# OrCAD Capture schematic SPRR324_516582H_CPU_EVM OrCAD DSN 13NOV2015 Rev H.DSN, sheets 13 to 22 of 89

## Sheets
13 SH19 - VAYU USB: size B; rev: A
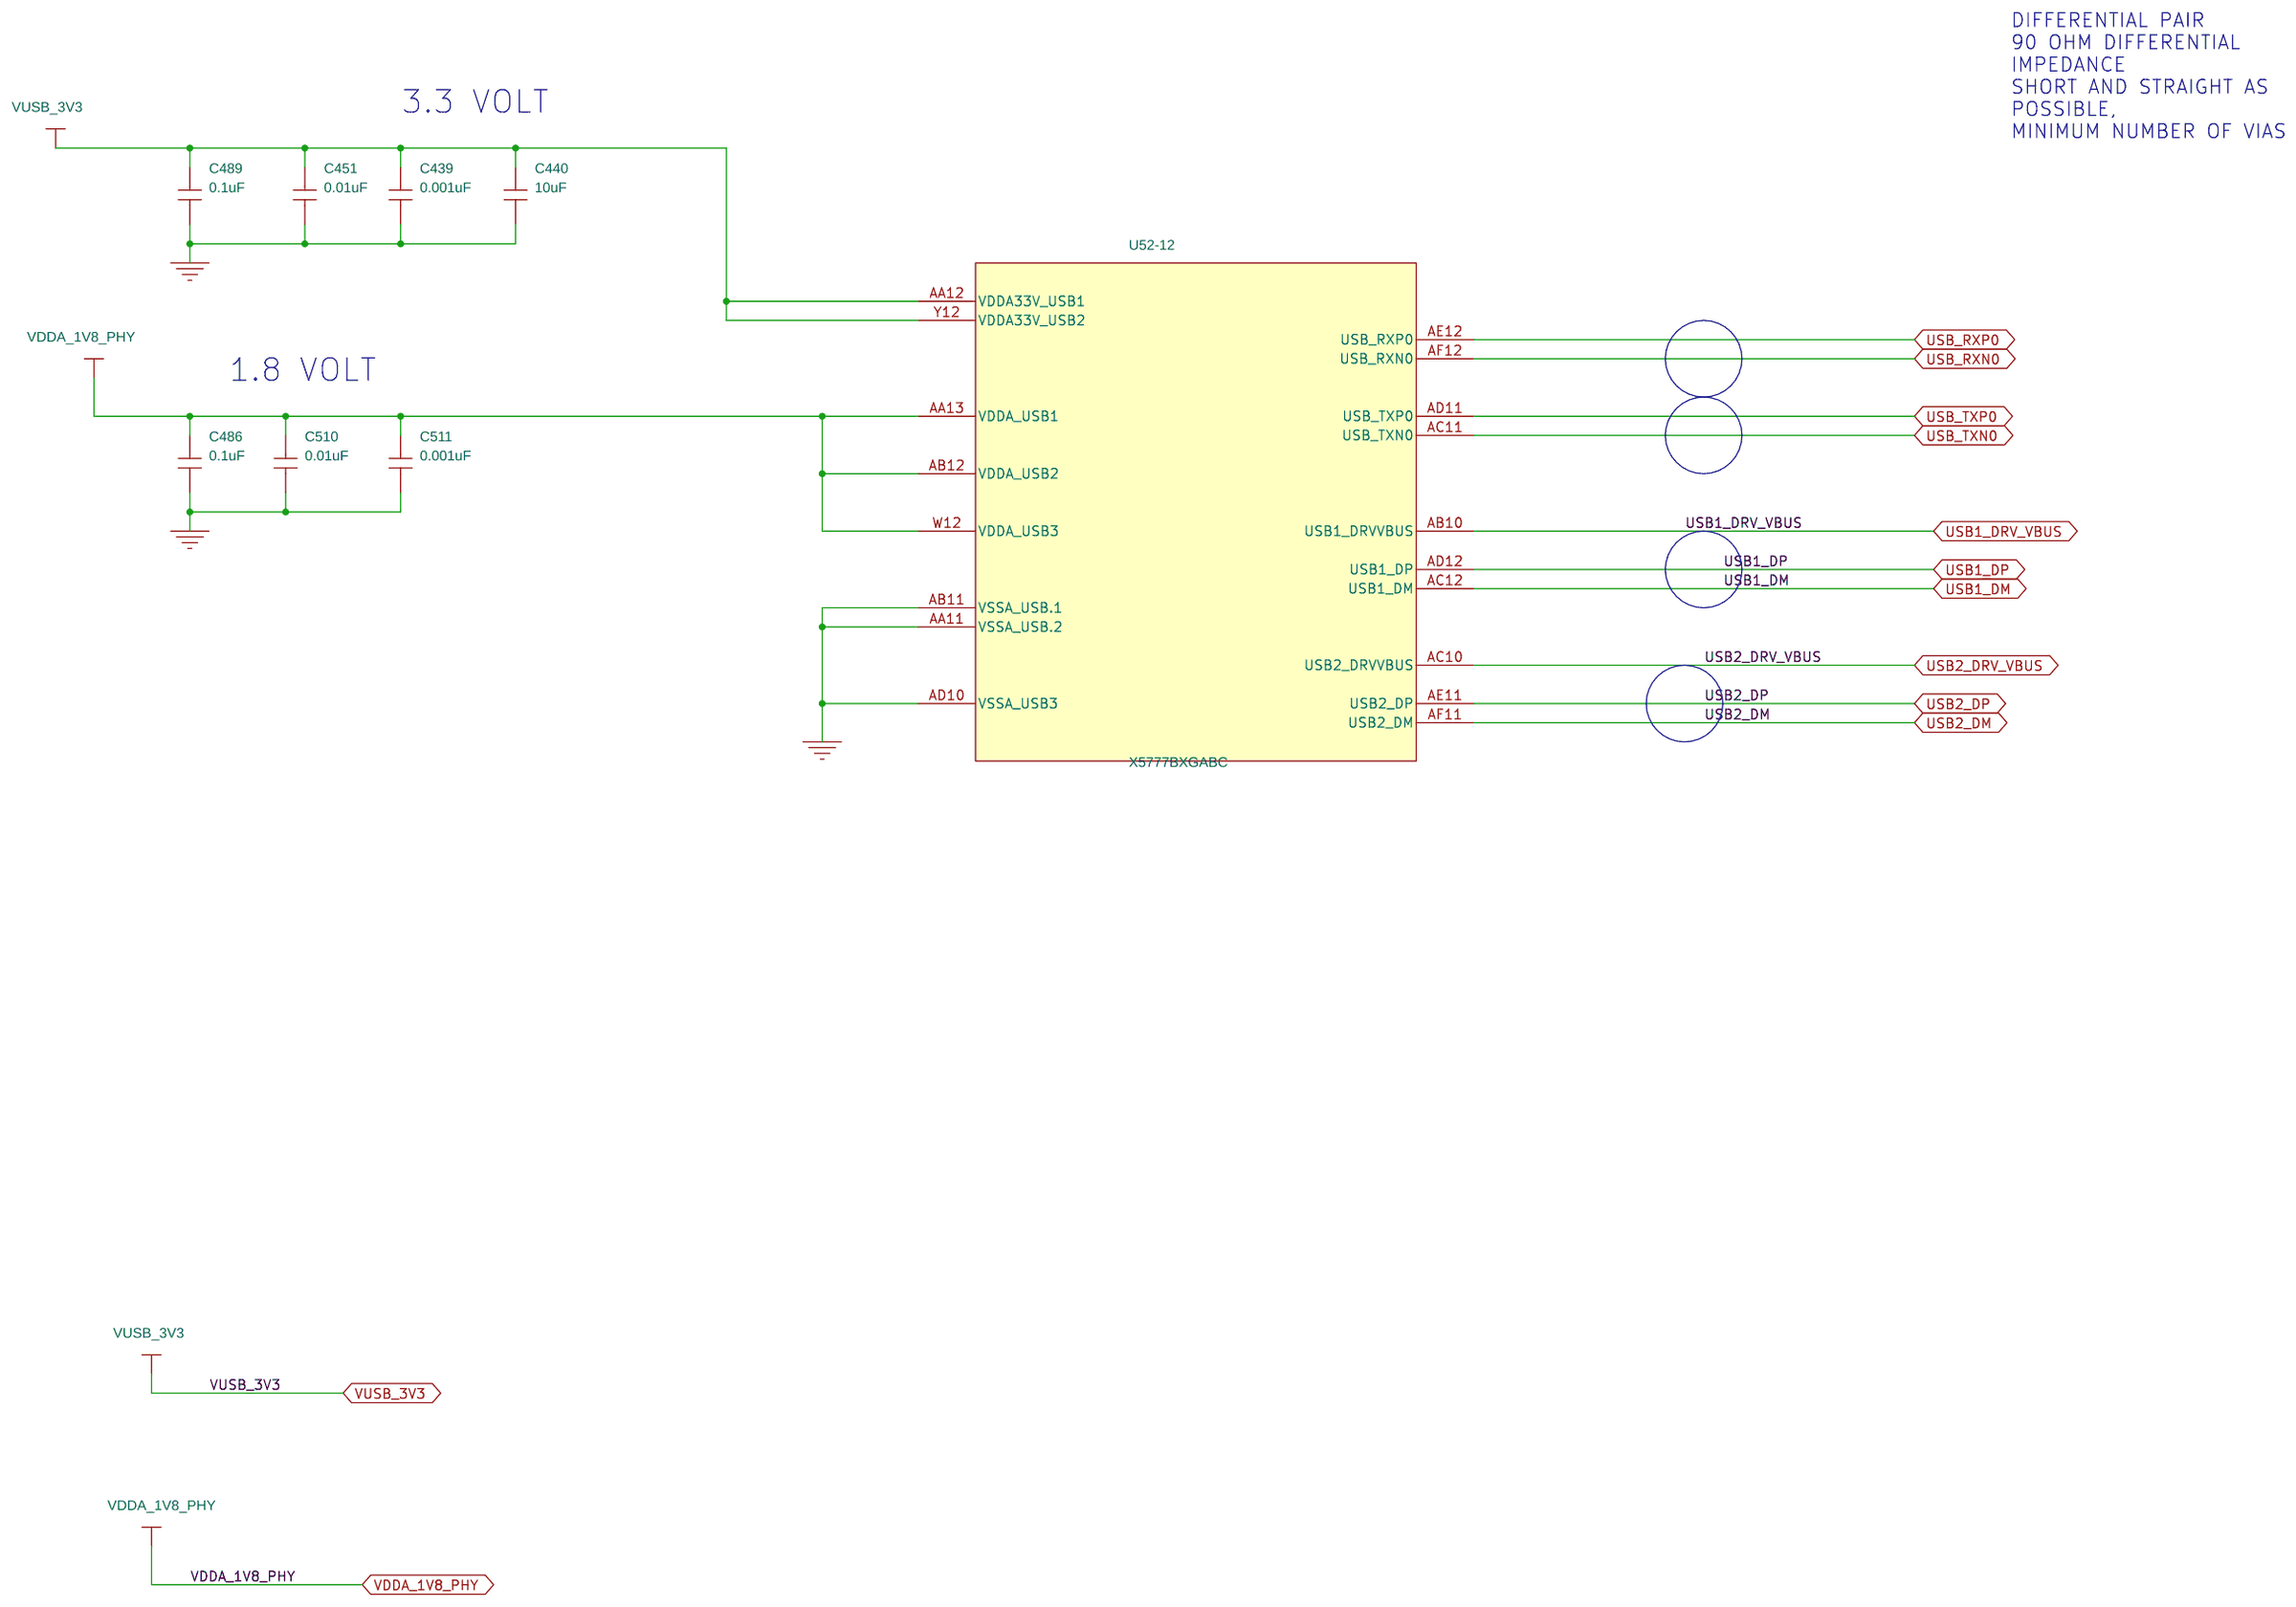
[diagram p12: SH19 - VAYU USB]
14 SH20 - VAYU GPMC: size B; rev: D2
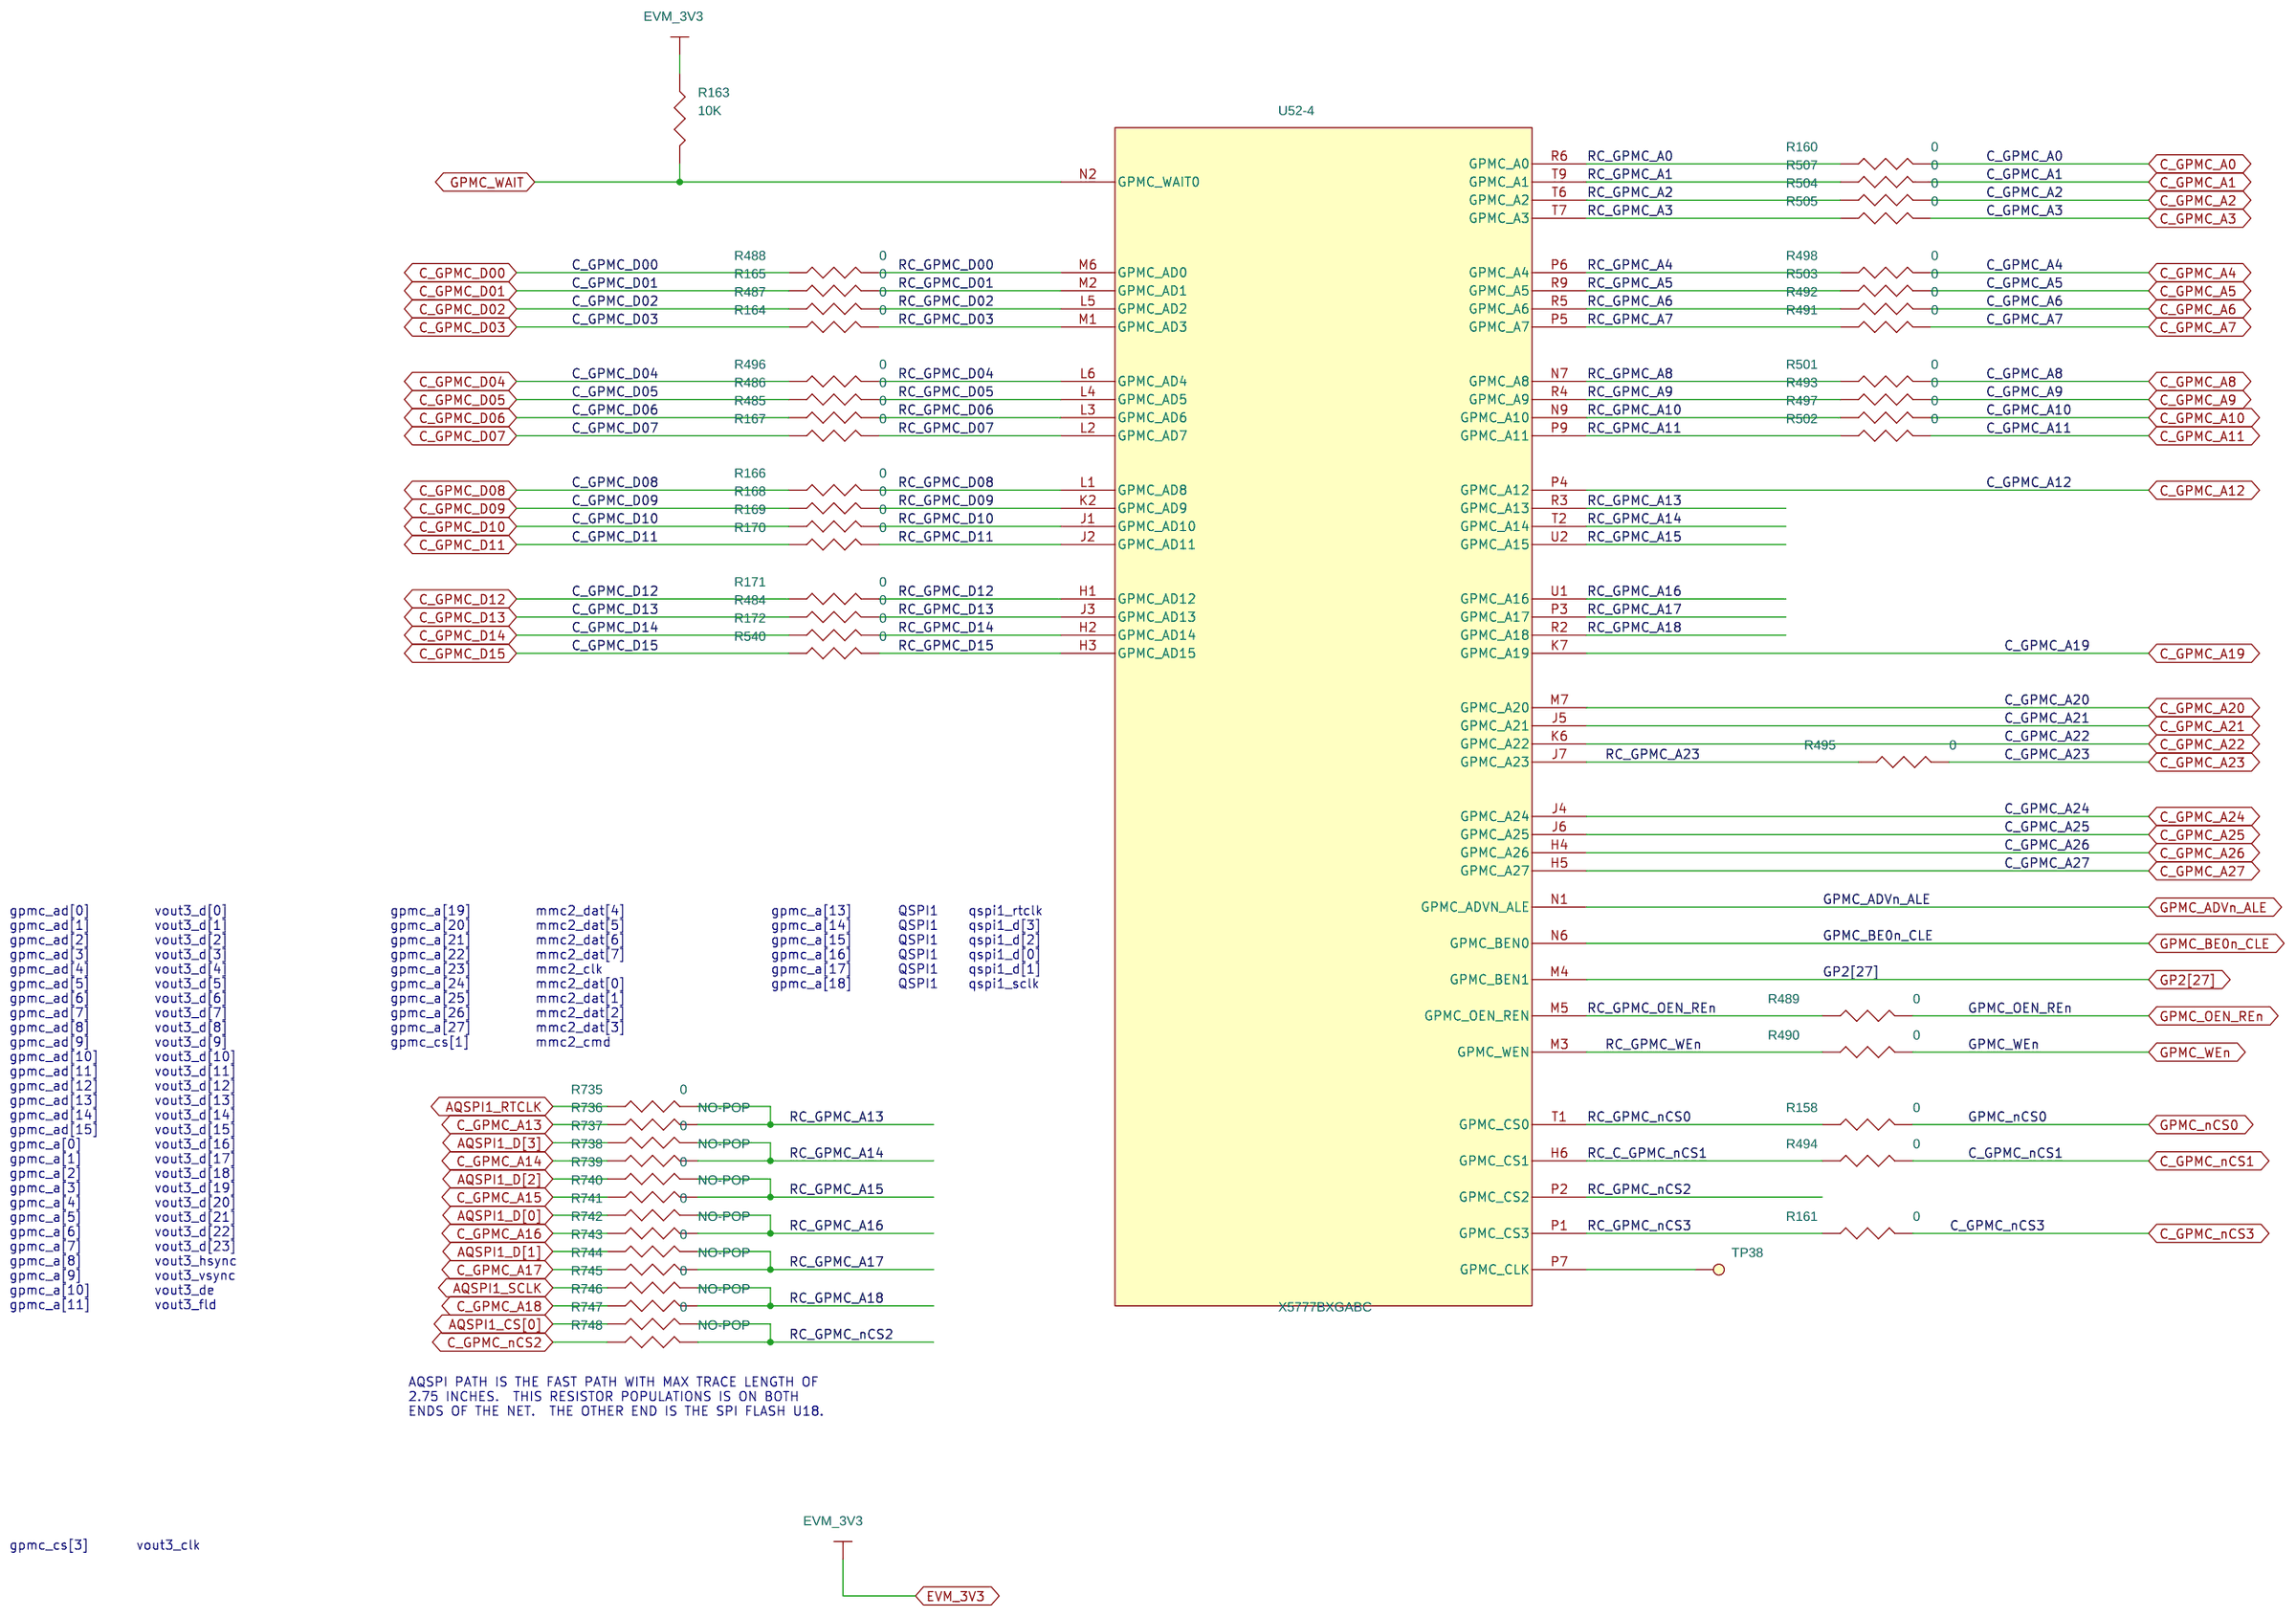
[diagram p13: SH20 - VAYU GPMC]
15 SH21 - GPMC DATA MUX VIDEO: size B; rev: A
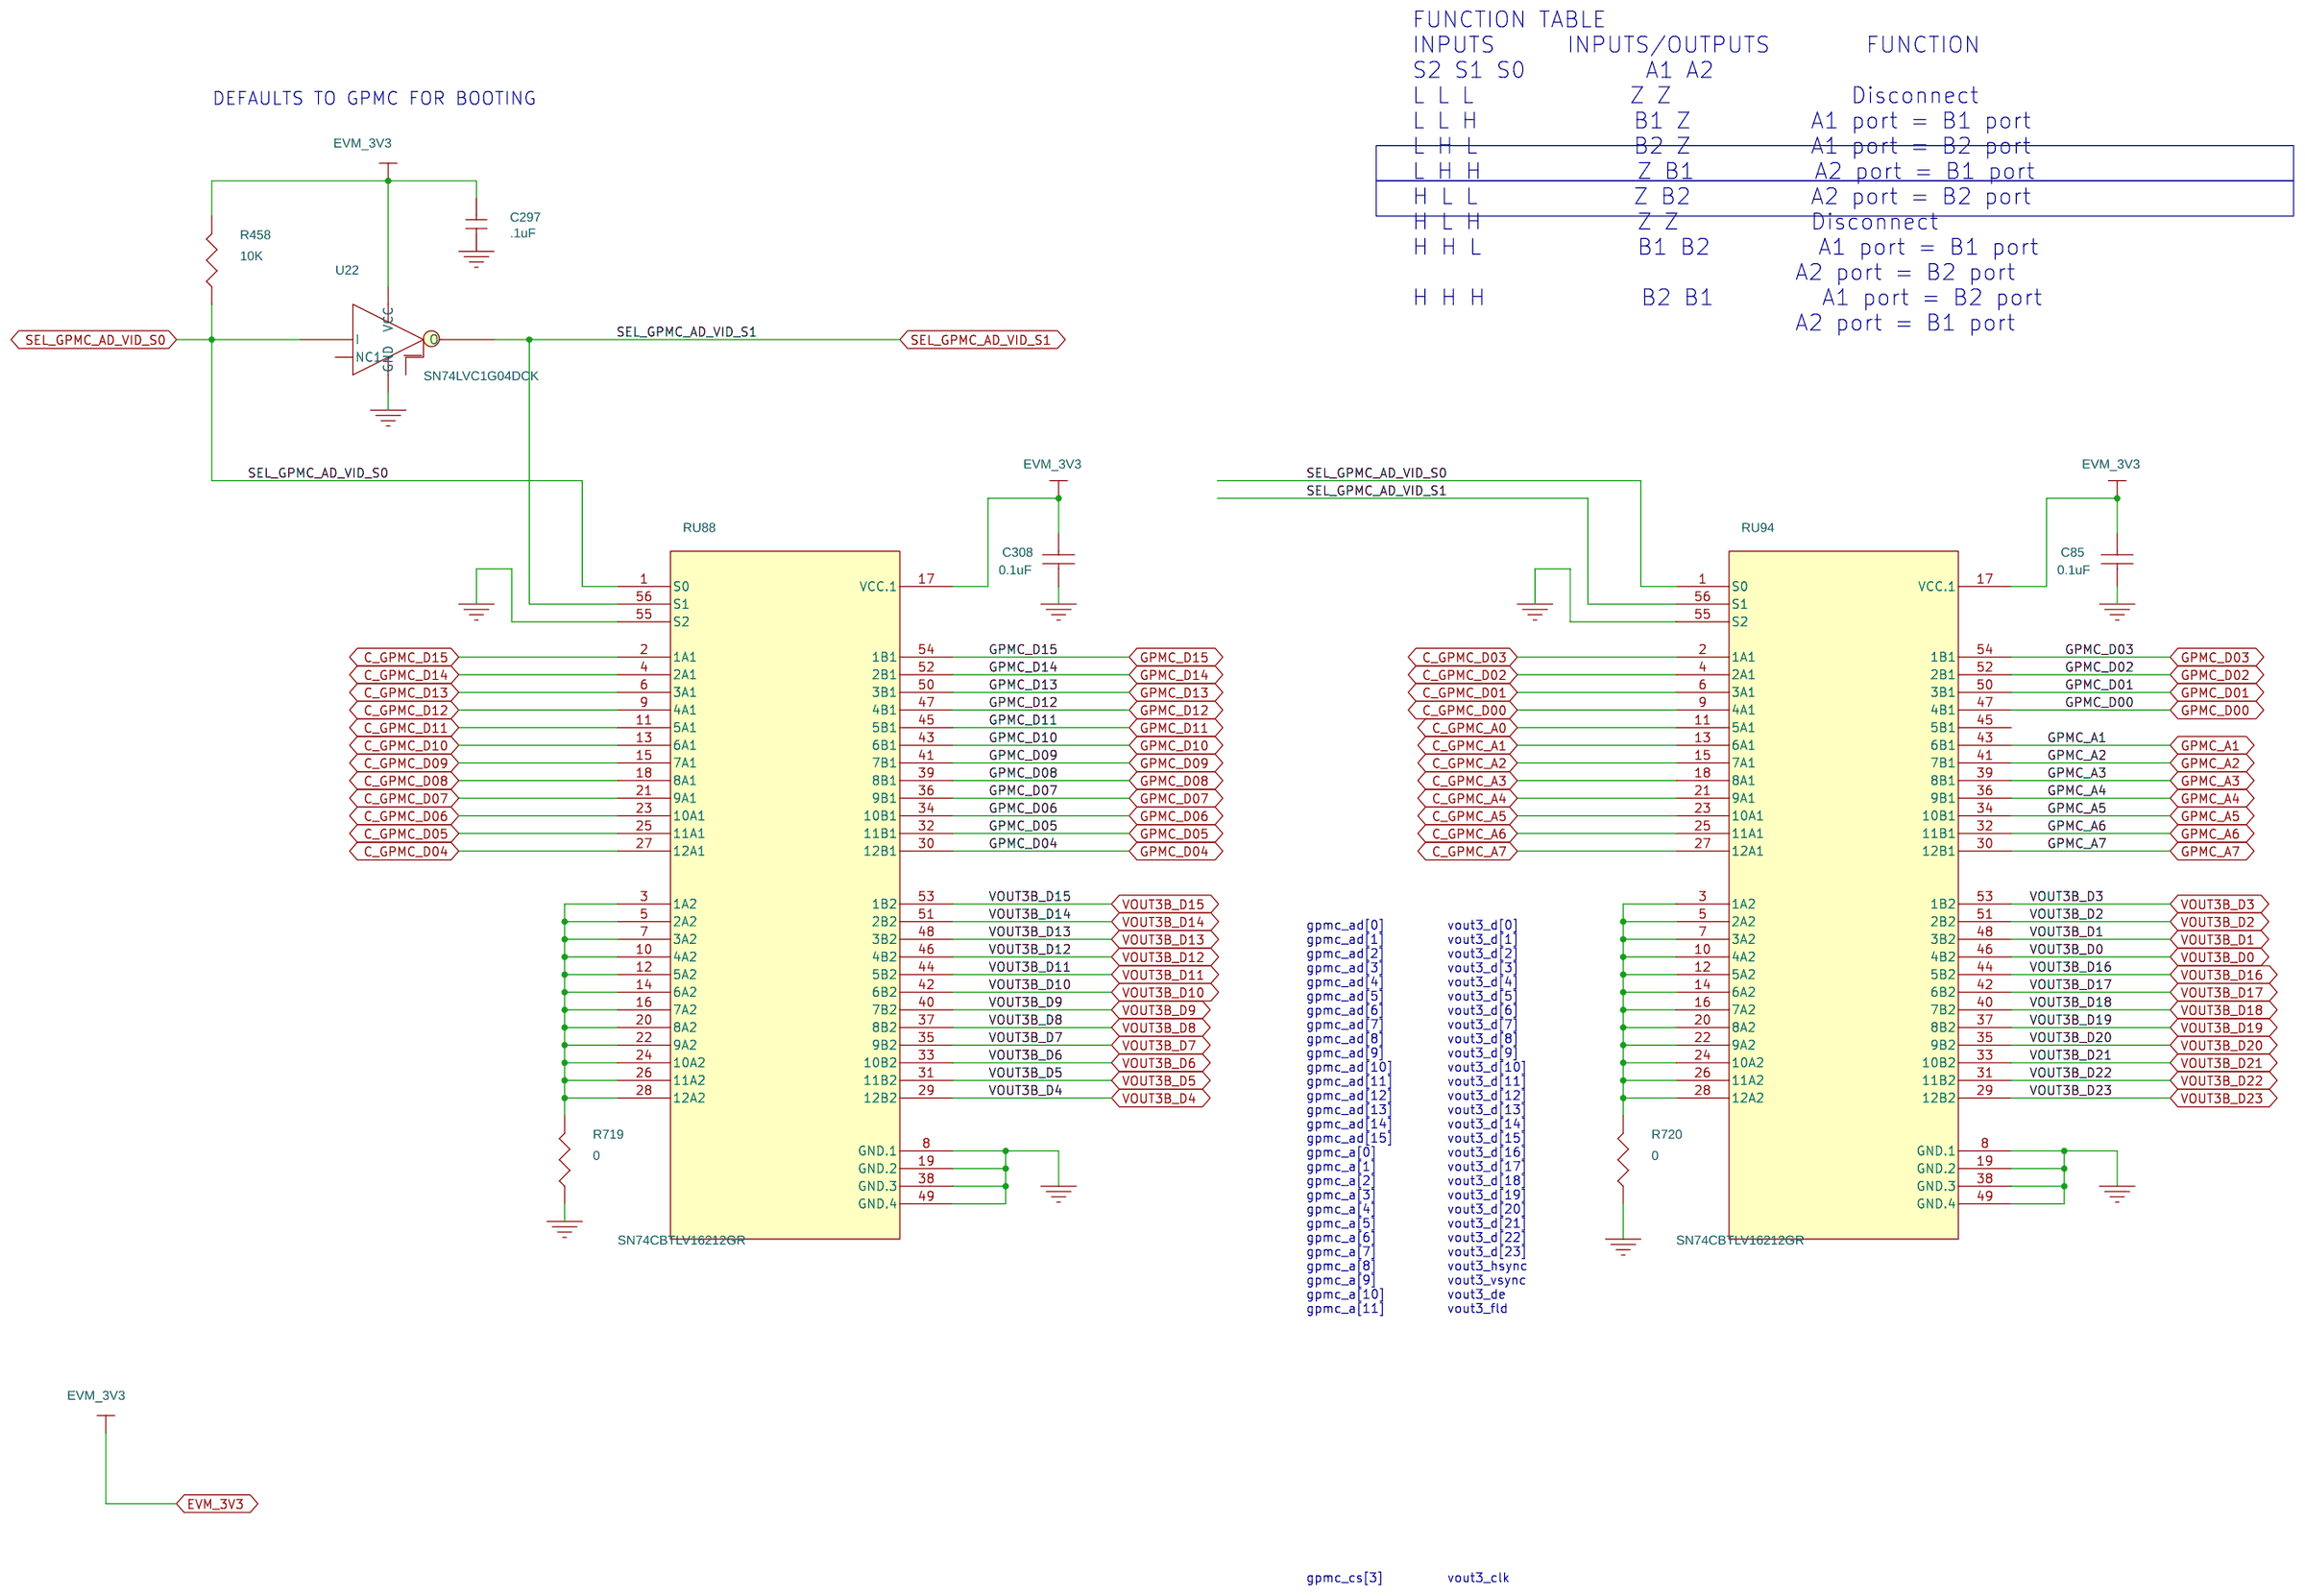
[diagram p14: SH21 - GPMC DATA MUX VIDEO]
16 SH22 - GPMC ADD MUX VIDEO: size B; rev: E
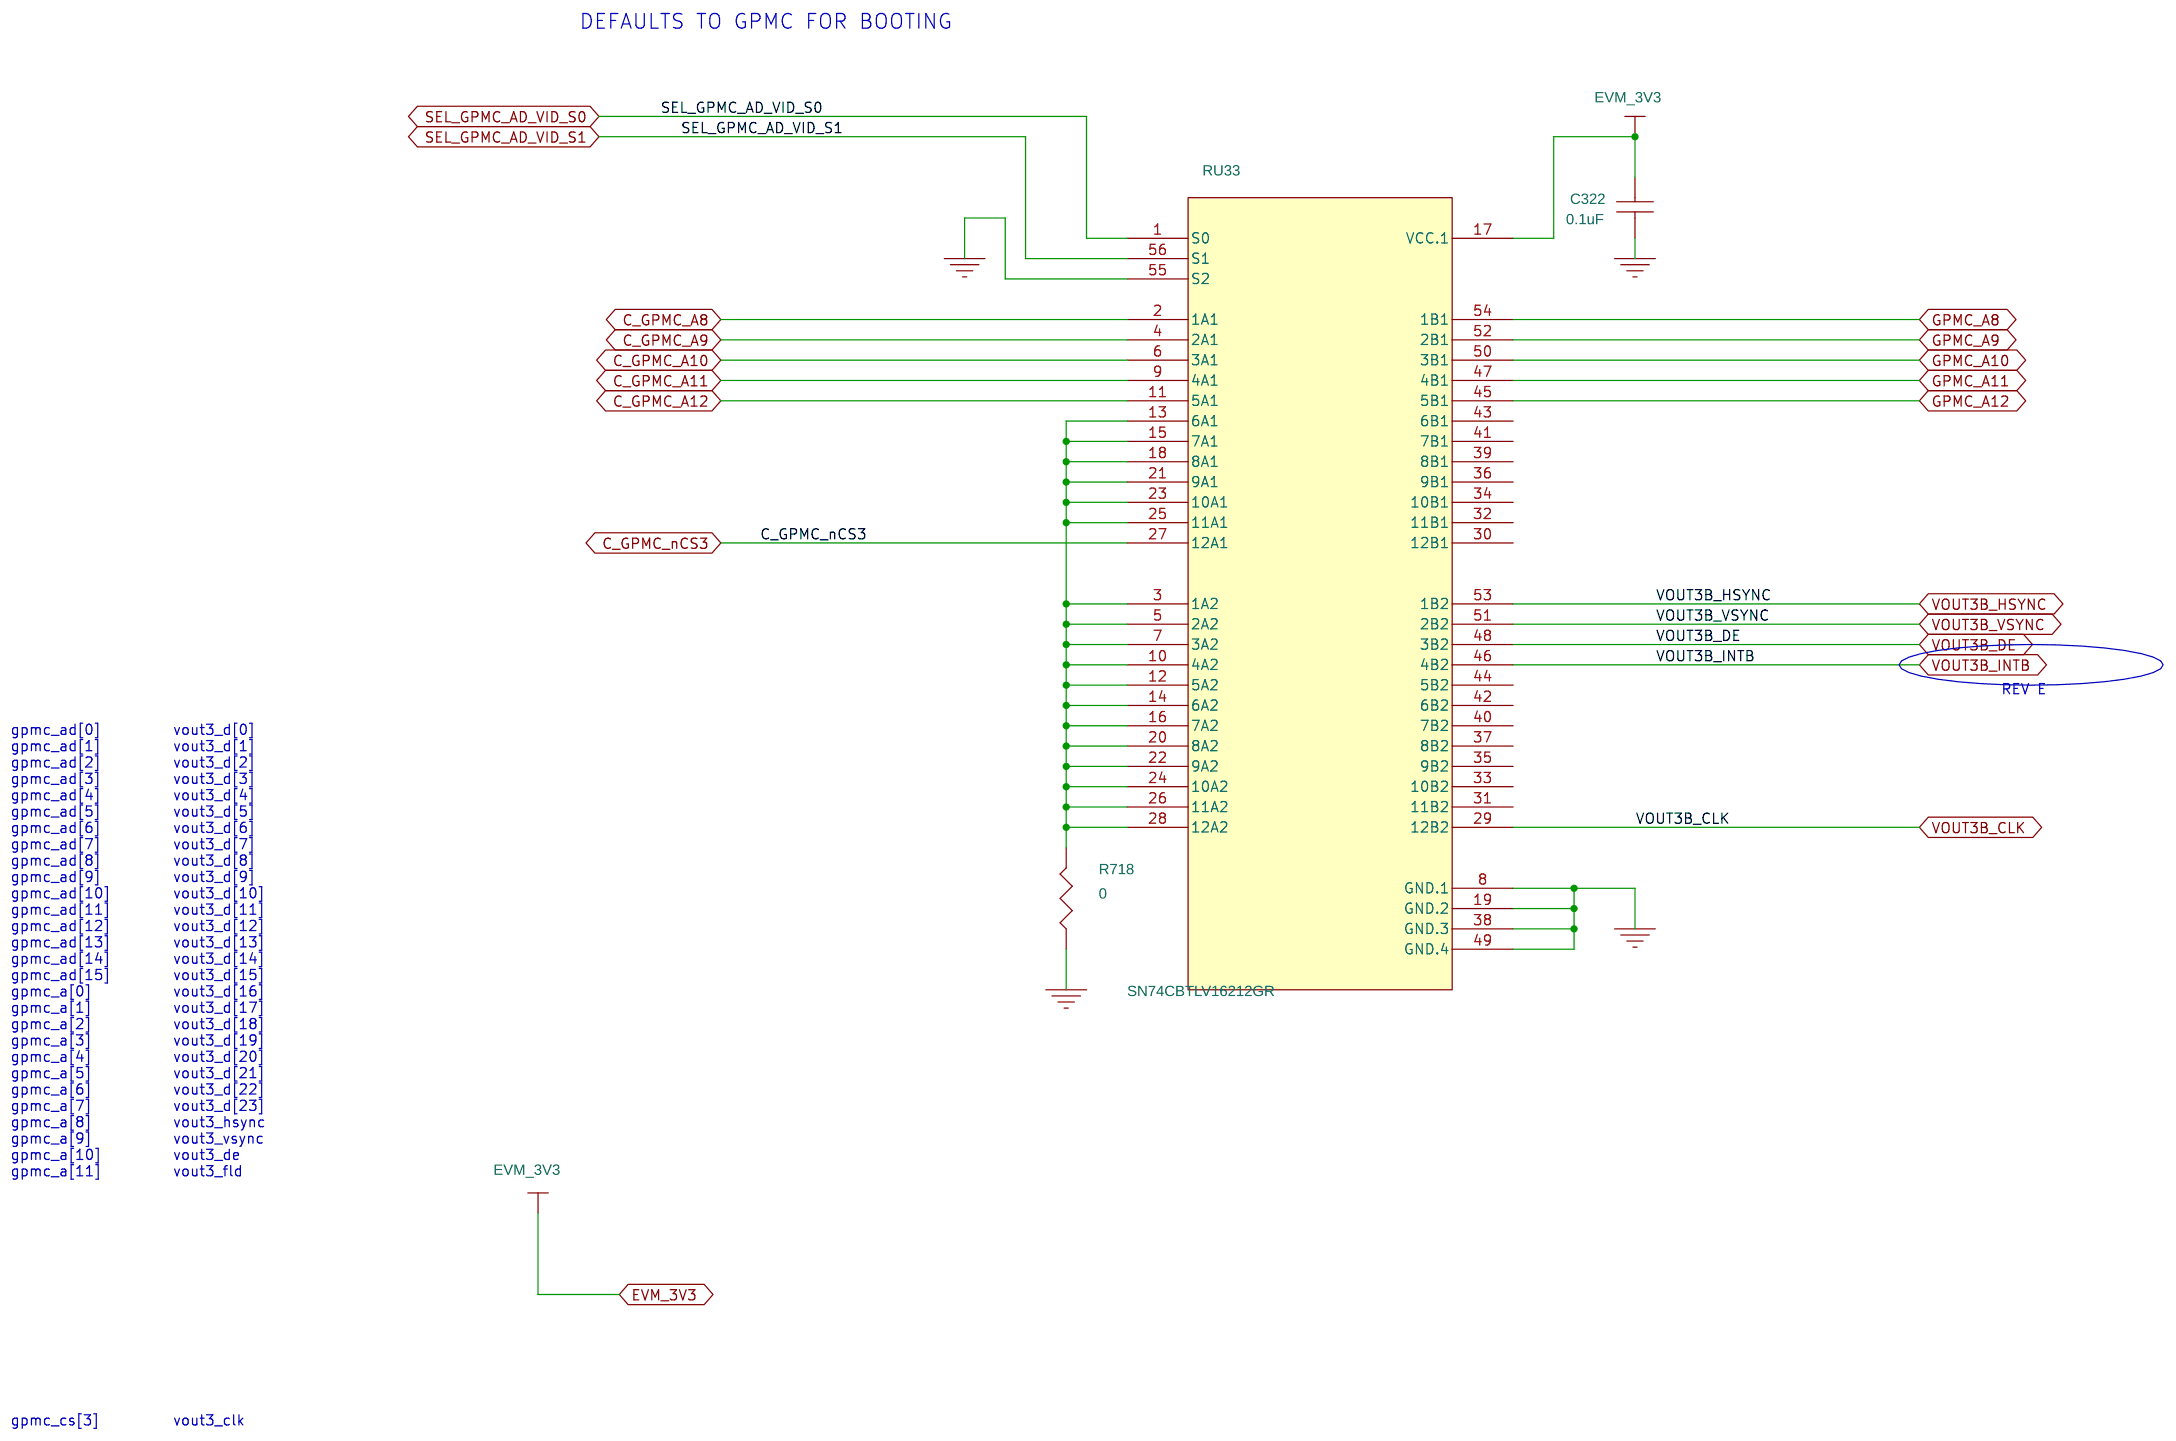
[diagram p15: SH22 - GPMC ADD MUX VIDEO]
17 SH23 - GPMC ADD MUX MMC: size B; rev: D2
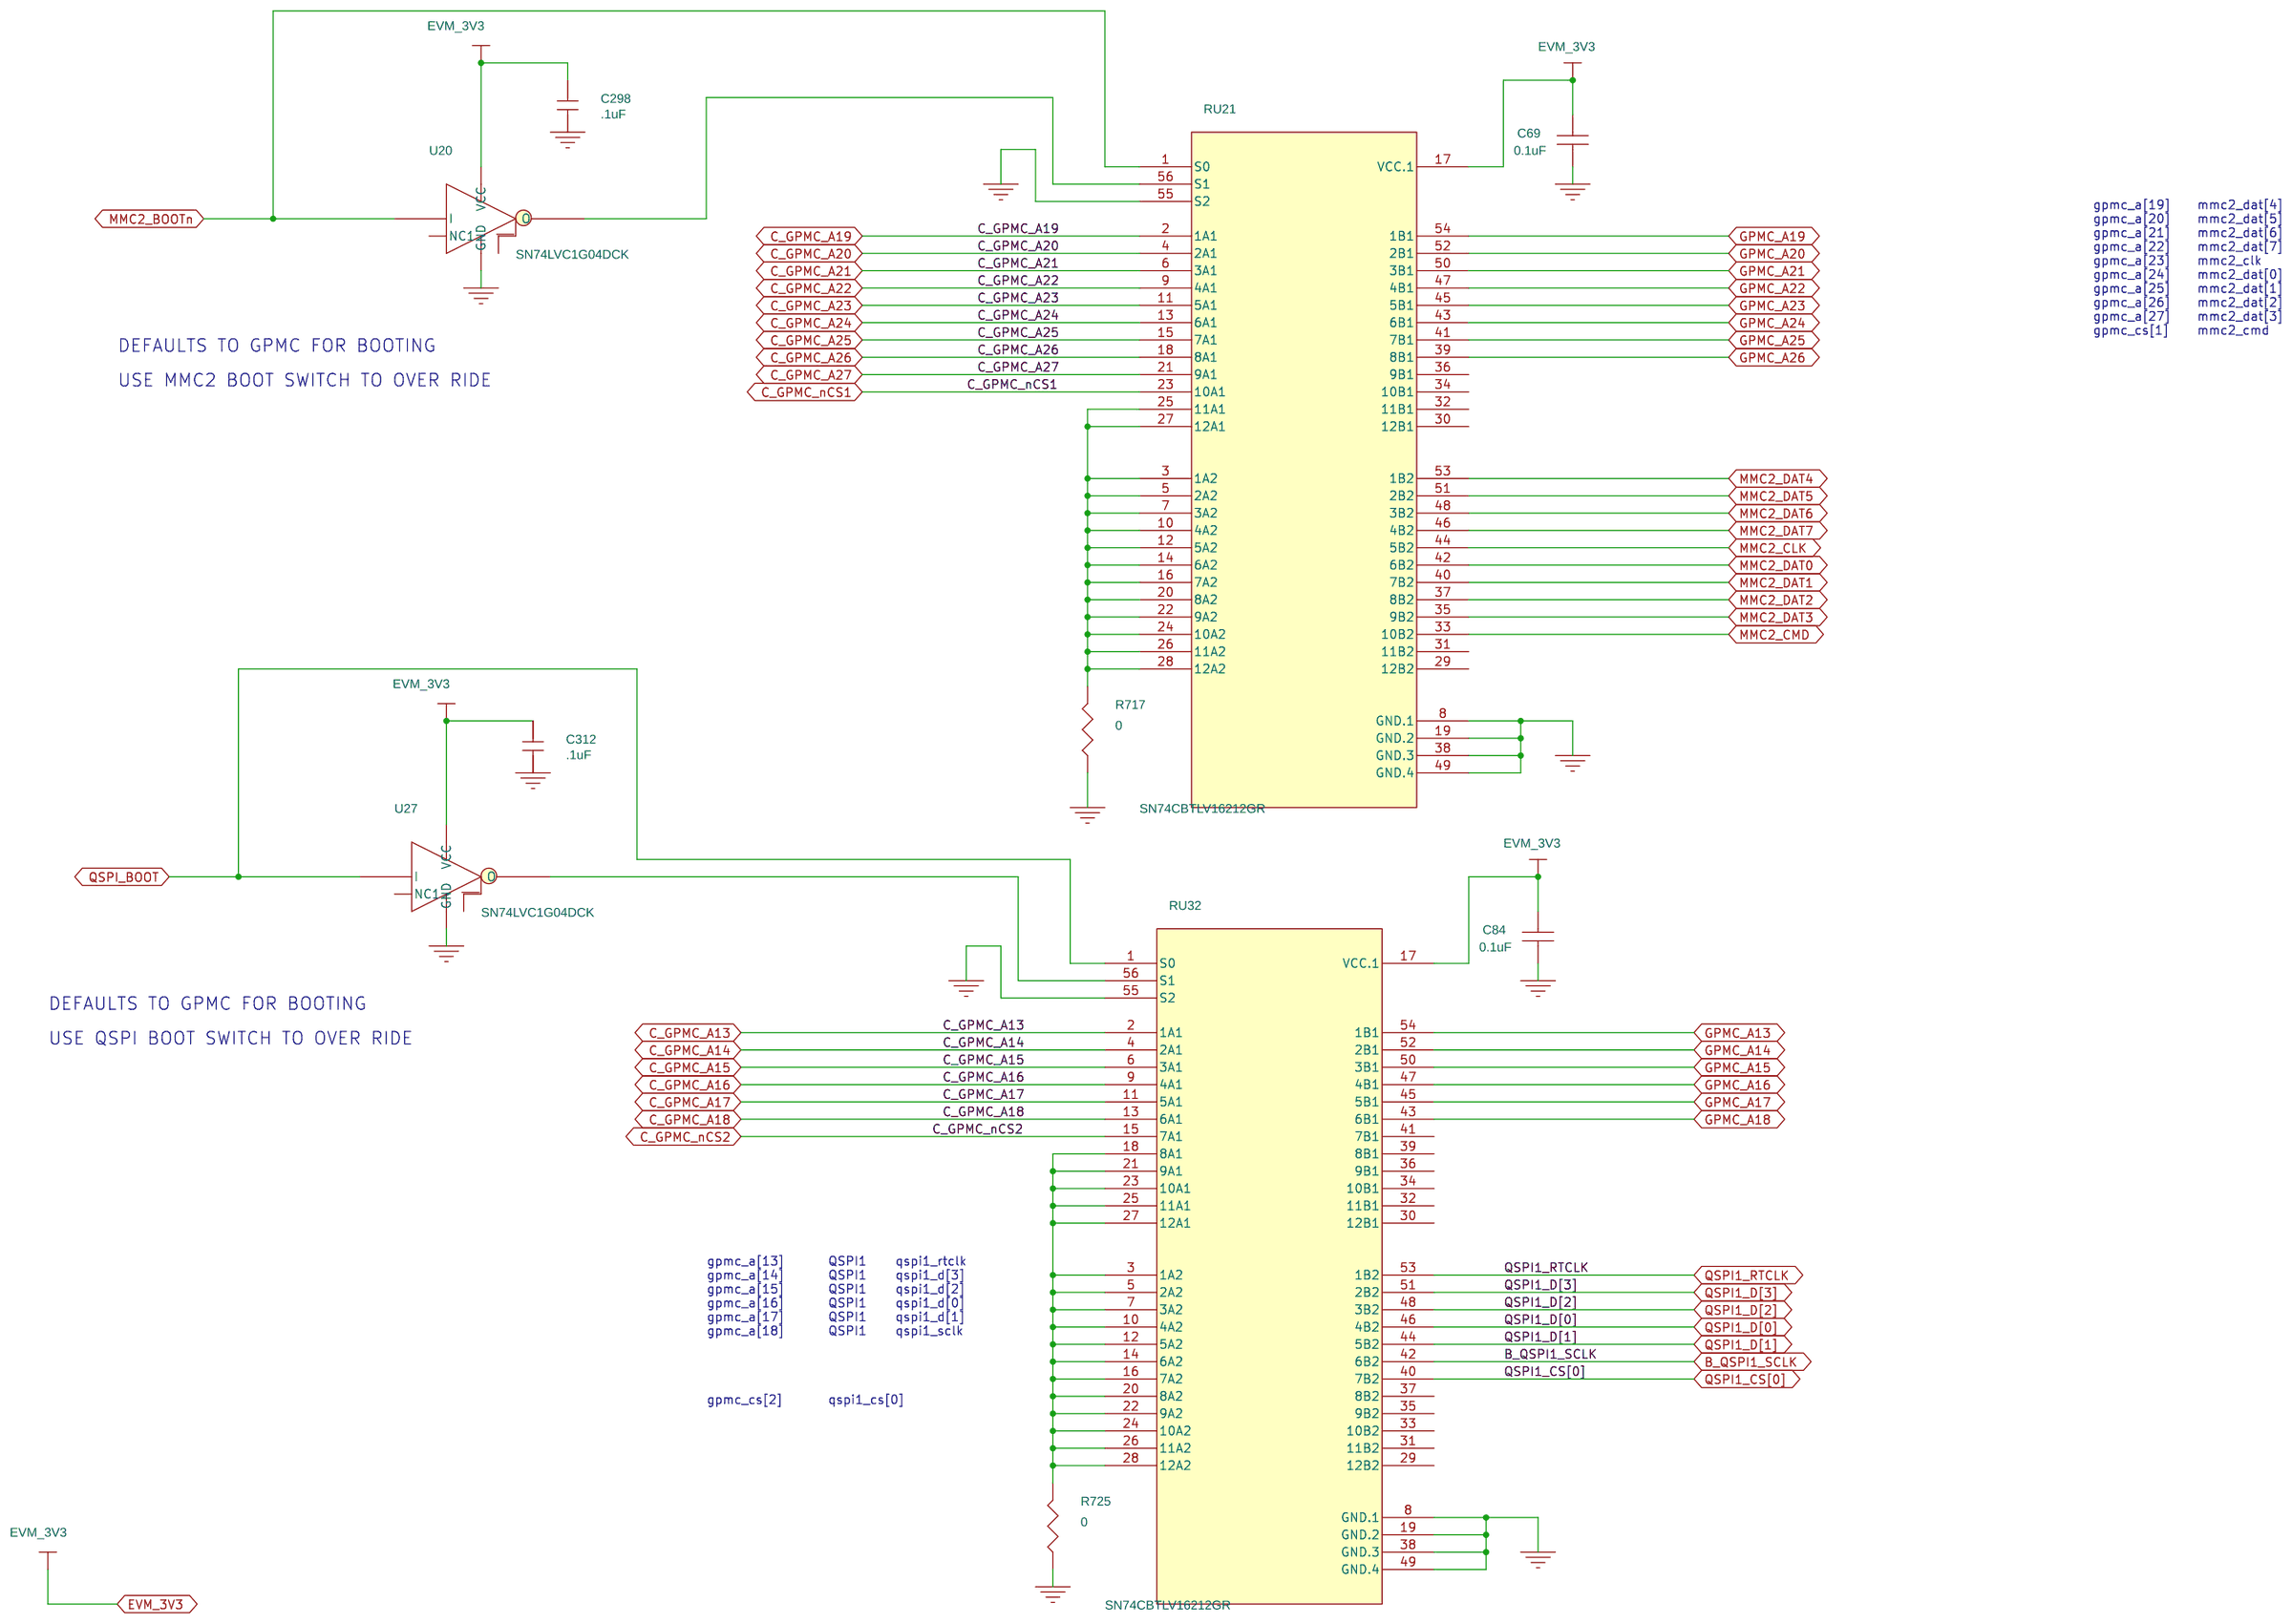
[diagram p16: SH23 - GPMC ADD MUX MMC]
18 SH24 - BOOTSWITCHES: size B; rev: B
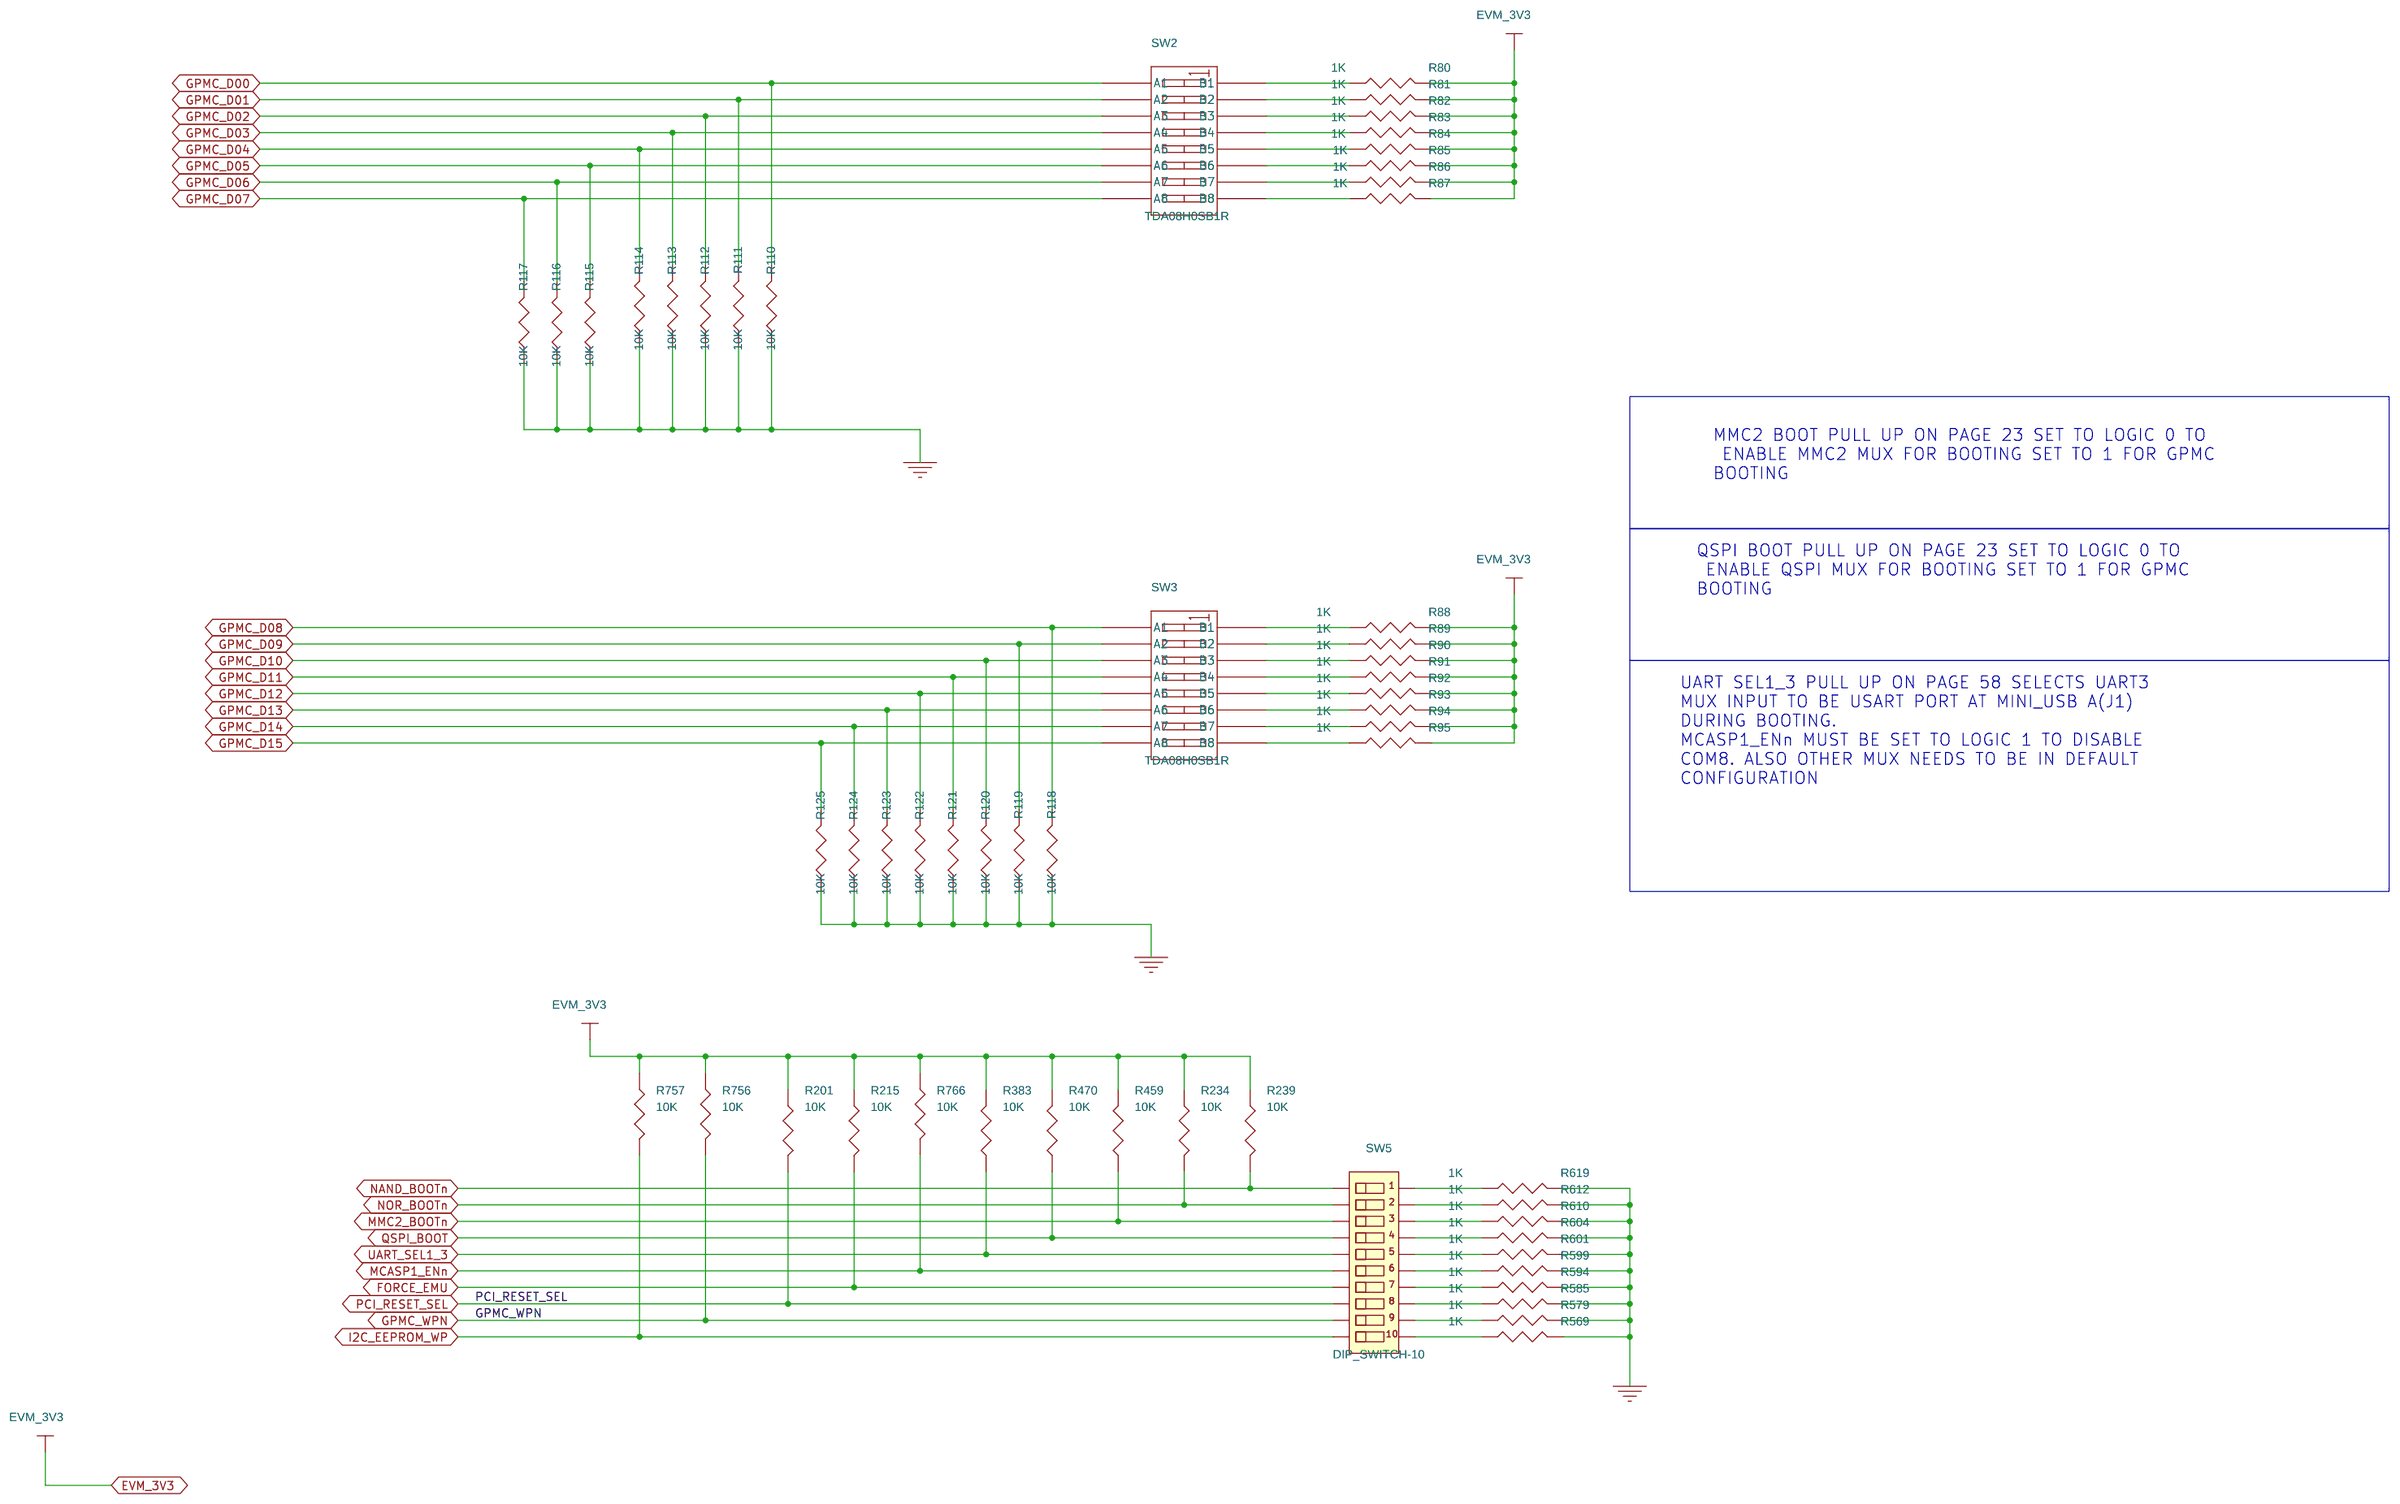
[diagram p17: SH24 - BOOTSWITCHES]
19 SH25 - VAYU DDR EMIF1 INTERFACE: size B; rev: A
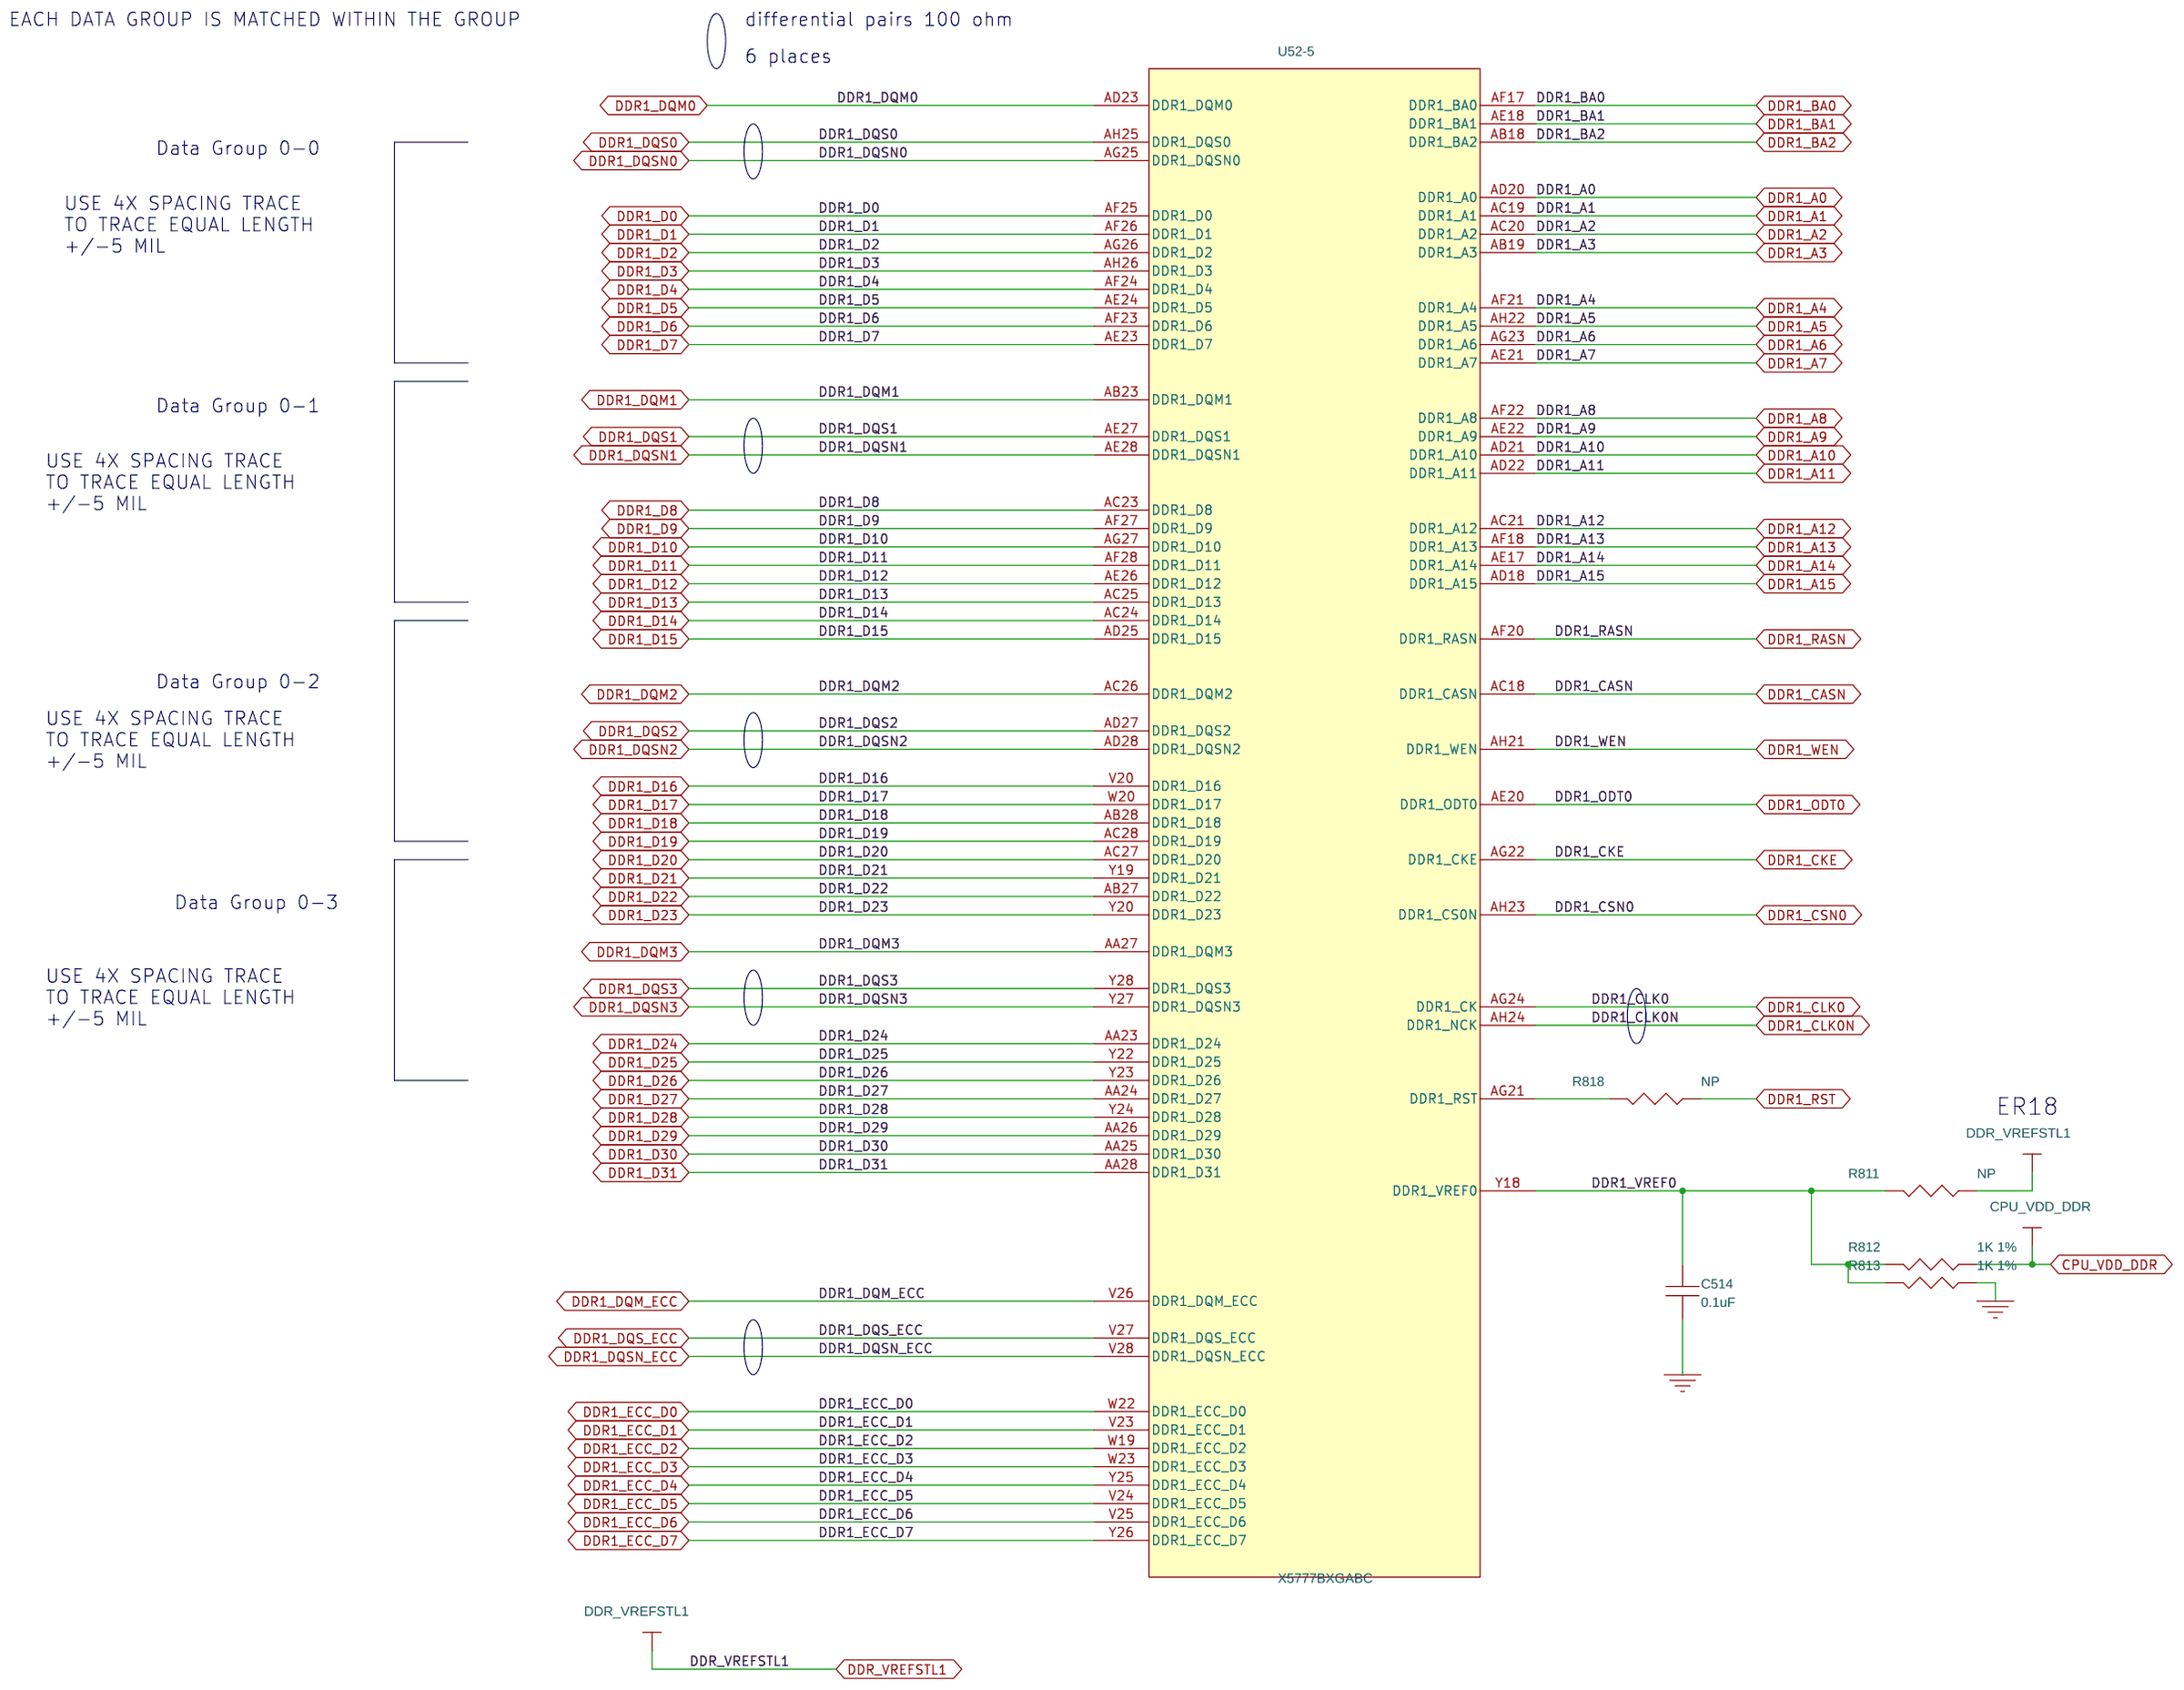
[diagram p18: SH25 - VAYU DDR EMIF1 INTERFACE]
20 SH26 - VAYU DDR EMIF2 INTERFACE: size B; rev: A
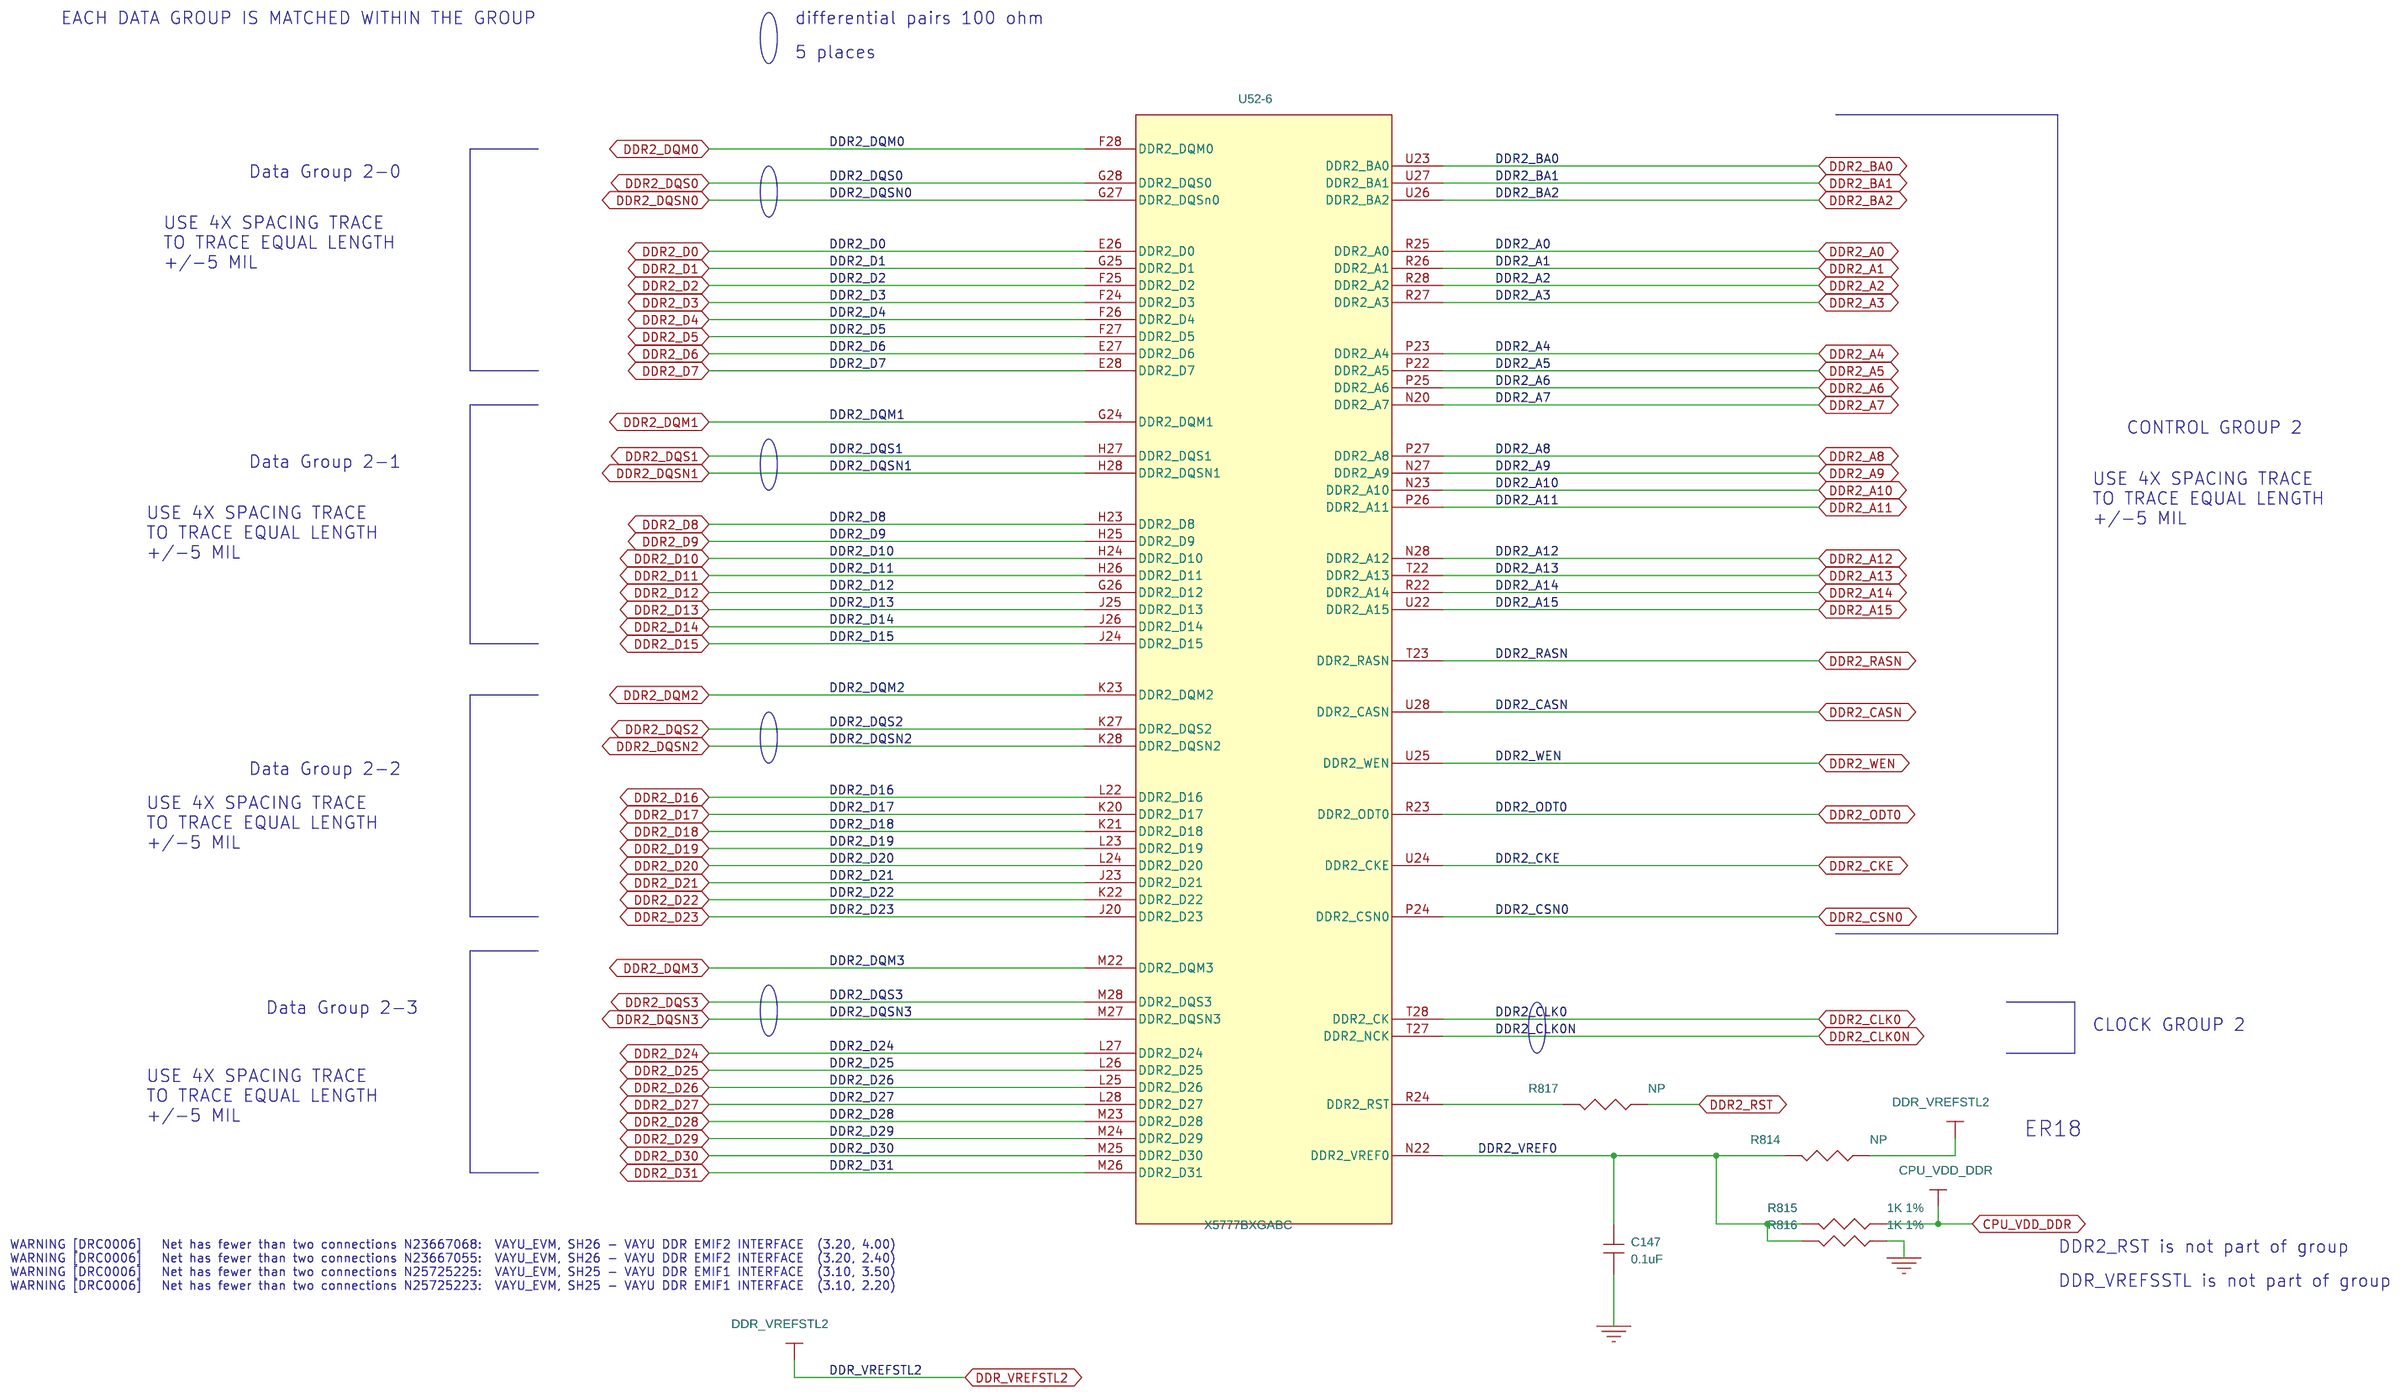
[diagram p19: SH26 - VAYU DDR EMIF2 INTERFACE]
21 SH27 - VAYU HDMI: size B; rev: A
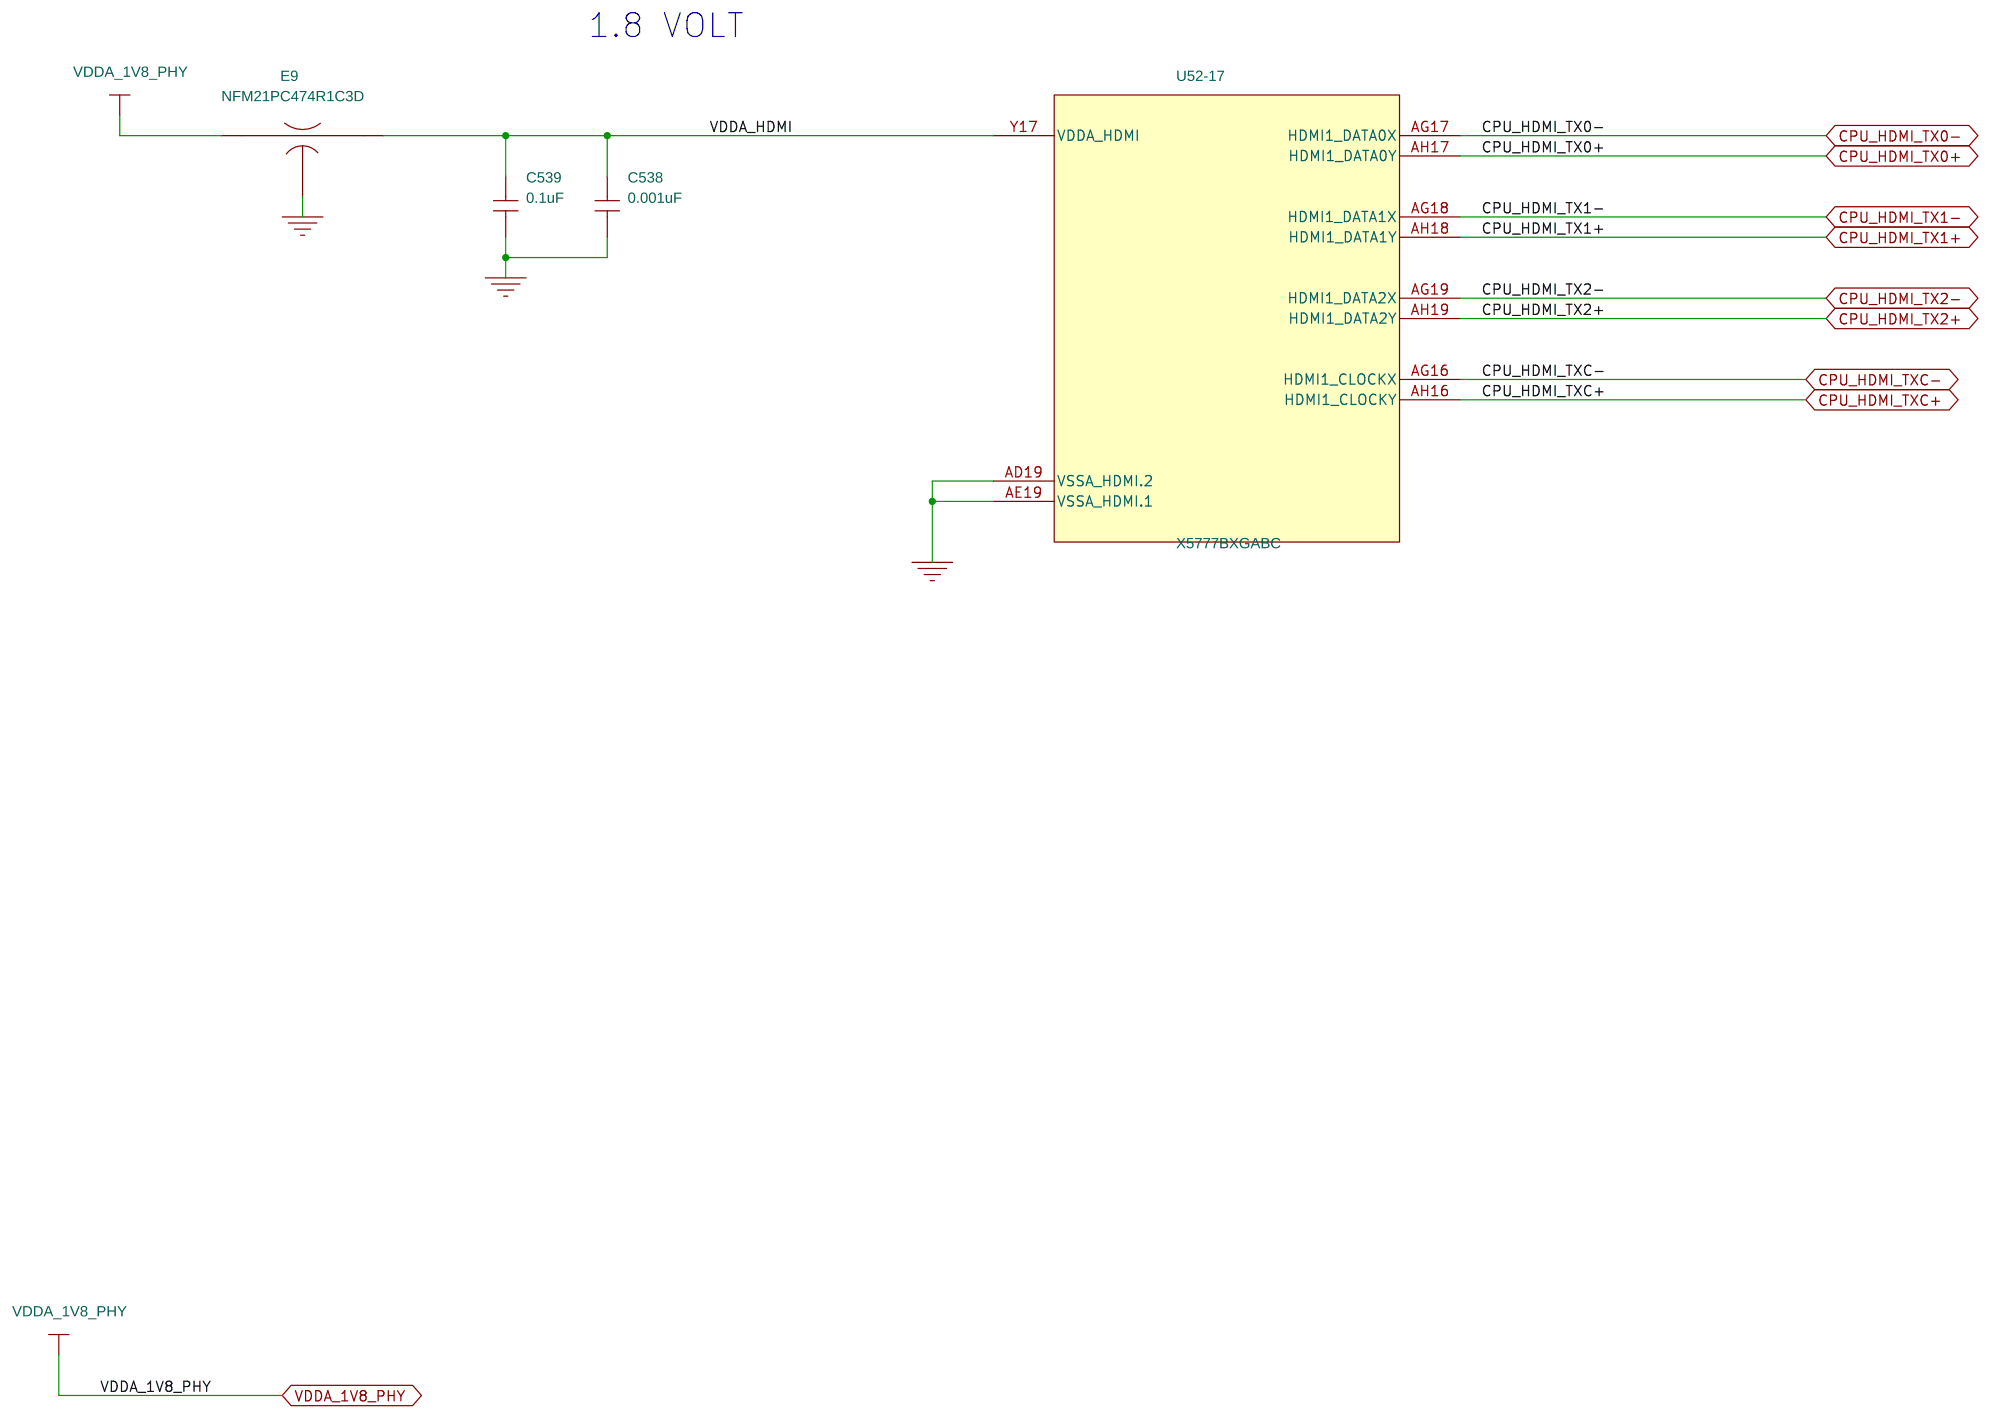
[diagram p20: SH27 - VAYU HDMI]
22 SH28 - VAYU VOUT1 PORT LCD: size B; rev: C
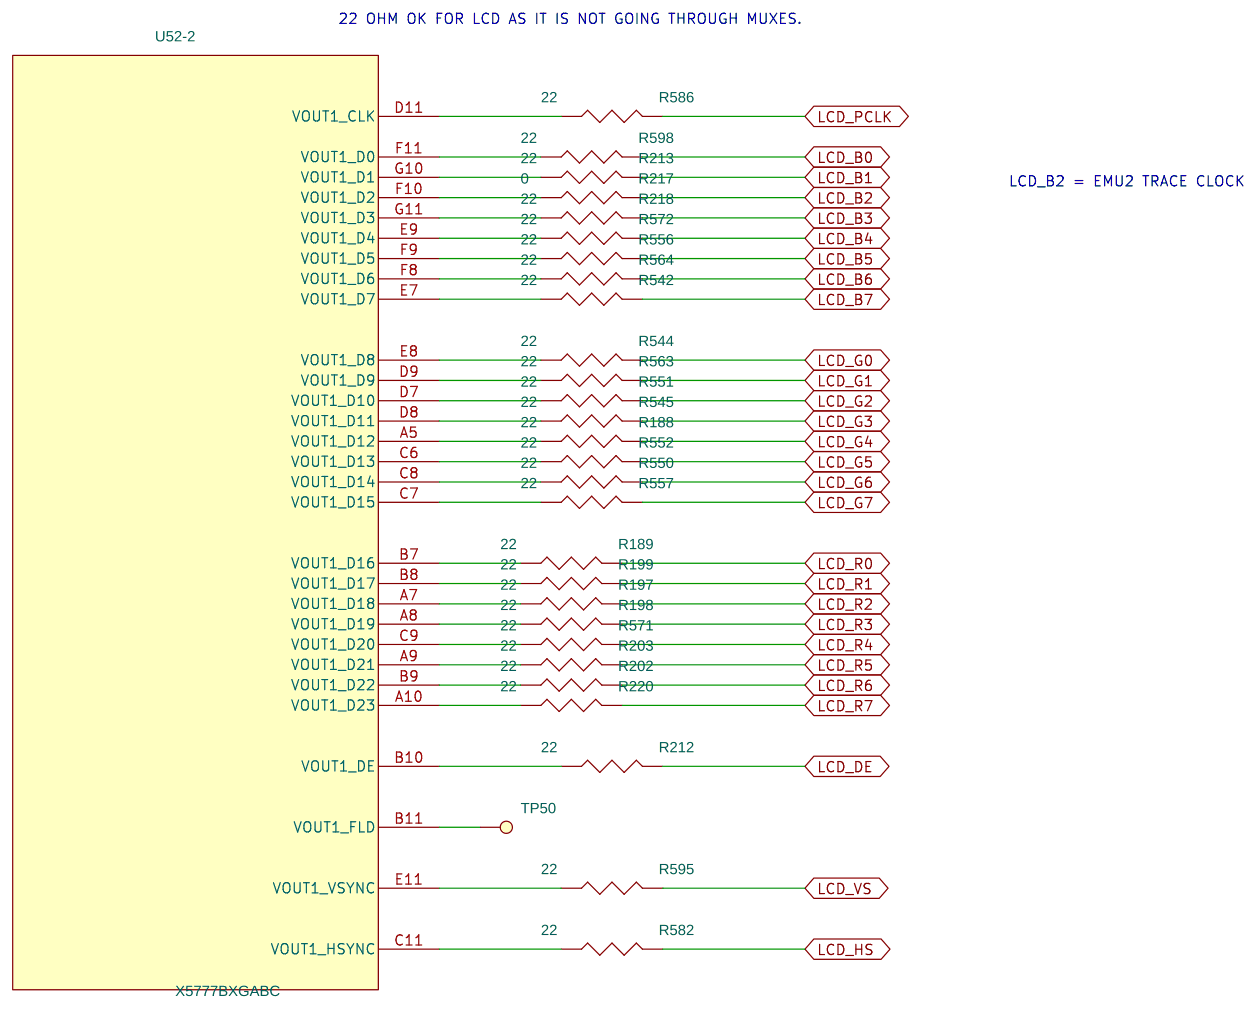
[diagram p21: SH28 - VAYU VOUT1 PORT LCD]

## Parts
sheet SH19 - VAYU USB
C439  0.001uF  [c201-6p6spc]
C440  10uF  [c603-35x45]
C451  0.01uF  [c201-6p6spc]
C486  0.1uF  [c201-6p6spc]
C489  0.1uF  [c201-6p6spc]
C510  0.01uF  [c201-6p6spc]
C511  0.001uF  [c201-6p6spc]
sheet SH20 - VAYU GPMC
R158  0  [r201-6p6spc]
R160  0  [r201-6p6spc]
R161  0  [r201-6p6spc]
R163  10K  [r201-6p6spc]
R164  0  [r201-6p6spc]
R165  0  [r201-6p6spc]
R166  0  [r201-6p6spc]
R167  0  [r201-6p6spc]
R168  0  [r201-6p6spc]
R169  0  [r201-6p6spc]
R170  0  [r201-6p6spc]
R171  0  [r201-6p6spc]
R172  0  [r201-6p6spc]
R484  0  [r201-6p6spc]
R485  0  [r201-6p6spc]
R486  0  [r201-6p6spc]
R487  0  [r201-6p6spc]
R488  0  [r201-6p6spc]
R489  0  [r201-6p6spc]
R490  0  [r201-6p6spc]
R491  0  [r201-6p6spc]
R492  0  [r201-6p6spc]
R493  0  [r201-6p6spc]
R494  0  [r201-6p6spc]
R495  0  [r201-6p6spc]
R496  0  [r201-6p6spc]
R497  0  [r201-6p6spc]
R498  0  [r201-6p6spc]
R501  0  [r201-6p6spc]
R502  0  [r201-6p6spc]
R503  0  [r201-6p6spc]
R504  0  [r201-6p6spc]
R505  0  [r201-6p6spc]
R507  0  [r201-6p6spc]
R540  0  [r201-6p6spc]
R735  0  [r402-25]
R736  NO-POP  [r402-25]
R737  0  [r402-25]
R738  NO-POP  [r402-25]
R739  0  [r402-25]
R740  NO-POP  [r402-25]
R741  0  [r402-25]
R742  NO-POP  [r402-25]
R743  0  [r402-25]
R744  NO-POP  [r402-25]
R745  0  [r402-25]
R746  NO-POP  [r402-25]
R747  0  [r402-25]
R748  NO-POP  [r402-25]
TP38  TestPoint1_0  [tp1-18rd8]
sheet SH21 - GPMC DATA MUX VIDEO
C85  0.1uF  [c402-25]
C297  .1uF  [c402-25]
C308  0.1uF  [c402-25]
R458  10K  [r201-6p6spc]
R719  0  [r201-6p6spc]
R720  0  [r201-6p6spc]
RU88  SN74CBTLV16212GR  [dgg56-12x80]
RU94  SN74CBTLV16212GR  [dgg56-12x80]
U22  SN74LVC1G04DCK  [dck-5]
sheet SH22 - GPMC ADD MUX VIDEO
C322  0.1uF  [c402-25]
R718  0  [r201-6p6spc]
RU33  SN74CBTLV16212GR  [dgg56-12x80]
sheet SH23 - GPMC ADD MUX MMC
C69  0.1uF  [c402-25]
C84  0.1uF  [c402-25]
C298  .1uF  [c402-25]
C312  .1uF  [c402-25]
R717  0  [r201-6p6spc]
R725  0  [r201-6p6spc]
RU21  SN74CBTLV16212GR  [dgg56-12x80]
RU32  SN74CBTLV16212GR  [dgg56-12x80]
U20  SN74LVC1G04DCK  [dck-5]
U27  SN74LVC1G04DCK  [dck-5]
sheet SH24 - BOOTSWITCHES
R80  1K  [r201-6p6spc]
R81  1K  [r201-6p6spc]
R82  1K  [r201-6p6spc]
R83  1K  [r201-6p6spc]
R84  1K  [r201-6p6spc]
R85  1K  [r201-6p6spc]
R86  1K  [r201-6p6spc]
R87  1K  [r201-6p6spc]
R88  1K  [r201-6p6spc]
R89  1K  [r201-6p6spc]
R90  1K  [r201-6p6spc]
R91  1K  [r201-6p6spc]
R92  1K  [r201-6p6spc]
R93  1K  [r201-6p6spc]
R94  1K  [r201-6p6spc]
R95  1K  [r201-6p6spc]
R110  10K  [r201-6p6spc]
R111  10K  [r201-6p6spc]
R112  10K  [r201-6p6spc]
R113  10K  [r201-6p6spc]
R114  10K  [r201-6p6spc]
R115  10K  [r201-6p6spc]
R116  10K  [r201-6p6spc]
R117  10K  [r201-6p6spc]
R118  10K  [r201-6p6spc]
R119  10K  [r201-6p6spc]
R120  10K  [r201-6p6spc]
R121  10K  [r201-6p6spc]
R122  10K  [r201-6p6spc]
R123  10K  [r201-6p6spc]
R124  10K  [r201-6p6spc]
R125  10K  [r201-6p6spc]
R201  10K  [r201-6p6spc]
R215  10K  [r201-6p6spc]
R234  10K  [r201-6p6spc]
R239  10K  [r201-6p6spc]
R383  10K  [r201-6p6spc]
R459  10K  [r201-6p6spc]
R470  10K  [r201-6p6spc]
R569  1K  [r201-6p6spc]
R579  1K  [r201-6p6spc]
R585  1K  [r201-6p6spc]
R594  1K  [r201-6p6spc]
R599  1K  [r201-6p6spc]
R601  1K  [r201-6p6spc]
R604  1K  [r201-6p6spc]
R610  1K  [r201-6p6spc]
R612  1K  [r201-6p6spc]
R619  1K  [r201-6p6spc]
R756  10K  [r201-6p6spc]
R757  10K  [r201-6p6spc]
R766  10K  [r201-6p6spc]
SW2  TDA08H0SB1R  [SW8-30X50]
SW3  TDA08H0SB1R  [SW8-30X50]
SW5  TDA10H0SK1  [SW10-30X50]
sheet SH25 - VAYU DDR EMIF1 INTERFACE
C514  0.1uF  [c201-6p6spc]
R811  NP  [r402-25]
R812  1K 1%  [r402-25]
R813  1K 1%  [r402-25]
R818  NP  [r402-25]
sheet SH26 - VAYU DDR EMIF2 INTERFACE
C147  0.1uF  [c201-6p6spc]
R814  NP  [r402-25]
R815  1K 1%  [r402-25]
R816  1K 1%  [r402-25]
R817  NP  [r402-25]
sheet SH27 - VAYU HDMI
C538  0.001uF  [c201-6p6spc]
C539  0.1uF  [c201-6p6spc]
E9  NFM21PC474R1C3D  [emi-NFM21p]
sheet SH28 - VAYU VOUT1 PORT LCD
R188  22  [r201-6p6spc]
R189  22  [r201-6p6spc]
R197  22  [r201-6p6spc]
R198  22  [r201-6p6spc]
R199  22  [r201-6p6spc]
R202  22  [r201-6p6spc]
R203  22  [r201-6p6spc]
R212  22  [r201-6p6spc]
R213  22  [r201-6p6spc]
R217  0  [r201-6p6spc]
R218  22  [r201-6p6spc]
R220  22  [r201-6p6spc]
R542  22  [r201-6p6spc]
R544  22  [r201-6p6spc]
R545  22  [r201-6p6spc]
R550  22  [r201-6p6spc]
R551  22  [r201-6p6spc]
R552  22  [r201-6p6spc]
R556  22  [r201-6p6spc]
R557  22  [r201-6p6spc]
R563  22  [r201-6p6spc]
R564  22  [r201-6p6spc]
R571  22  [r201-6p6spc]
R572  22  [r201-6p6spc]
R582  22  [r201-6p6spc]
R586  22  [r201-6p6spc]
R595  22  [r201-6p6spc]
R598  22  [r201-6p6spc]
TP50  TestPoint1_0  [tp1-18rd8]
U52  X5777BXGABC  [sktbga-zkk-6334-p760]  (sections -1,-10,-11,-12,-13,-14,-15,-16,-17,-18,-19,-2,-20,-21,-22,-23,-3,-4,-5,-6,-7,-8,-9)

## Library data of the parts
C439 C511 C538 = CAP_NP: Part #: 103367-1102R
C440 = CAP_NP: Part #: 102963-0101R
C451 C510 = CAP_NP: Part #: 103241-1101R
C147 C486 C489 C539 = CAP_NP: Part #: 103241-1100R
R158 R160 R161 R164-R172 R217 R484-R498 R501-R505 R507 R540 R717-R720 R725 = R: Part #: 103158-0001R
R163 R201 R215 R234 R239 R383 R458 R459 R470 R756 R757 R766 = R: Part #: 103158-1003R
R735 R737 R739 R741 R743 R745 R747 = R: Part #: 101370-0001R
R736 R738 R740 R742 R744 R746 R748 R818 = R: Part #: R0402-NOPOP
TP38 TP50 = TestPoint1_0: Part #: TP-18RD8-NO-POP
C69 C84 C85 C308 C322 = CAP: Part #: 101587-1100R
C297 C298 C312 = CAP_NP: Part #: 101587-1100R
RU21 RU32 RU33 RU88 RU94 = SN74CBT16212DGGR: Part #: 102693-0001R
U20 U22 U27 = SN74LVC1GU04_1: Part #: 101057-0004R
R80-R95 R569 R579 R585 R594 R599 R601 R604 R610 R612 R619 = R_1: Part #: 103158-1002R
R110-R125 = R_1: Part #: 103158-1003R
SW2 SW3 = SW_DIP-8: Part #: 101184-0008R
SW5 = DIP_SWITCH_10: 10POS Dip Switch Half Pitch SMT; Comment: DIP_SWITCH-10; Mfgr: C & K; Part #: 101184-0010R; Vendor: Digi-Key; Vendor Nbr: CKN1366-ND
C514 = CAP: Part #: 103241-1100R
R811 R814 R817 = R: Part #: r0402-nopop
R812 R813 R815 R816 = R: Part #: 102145-1002R
E9 = NFM_1: Part #: 102569-1470R
R188 R189 R197-R199 R202 R203 R212 R213 R218 R220 R542 R544 R545 R550-R552 R556 R557 R563 R564 R571 R572 R582 R586 R595 R598 = R: Part #: 103158-2200R
U52 = VAYU_DEC_3_2: Part #: 104183-0003R

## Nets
GND: C69.2 C84.2 C85.2 C147.2 C297.2 C298.2 C308.2 C312.2 C322.2 C439.2 C440.2 C451.2 C486.2 C489.2 C510.2 C511.2 C514.2 C538.2 C539.2 E9.2 R110.2 R111.2 R112.2 R113.2 R114.2 R115.2 R116.2 R117.2 R118.2 R119.2 R120.2 R121.2 R122.2 R123.2 R124.2 R125.2 R569.1 R579.1 R585.1 R594.1 R599.1 R601.1 R604.1 R610.1 R612.1 R619.1 R717.1 R718.1 R719.1 R720.1 R725.1 R813.1 R816.1 RU21.8(GND.1) RU21.19(GND.2) RU21.38(GND.3) RU21.49(GND.4) RU21.55(S2) RU32.8(GND.1) RU32.19(GND.2) RU32.38(GND.3) RU32.49(GND.4) RU32.55(S2) RU33.8(GND.1) RU33.19(GND.2) RU33.38(GND.3) RU33.49(GND.4) RU33.55(S2) RU88.8(GND.1) RU88.19(GND.2) RU88.38(GND.3) RU88.49(GND.4) RU88.55(S2) RU94.8(GND.1) RU94.19(GND.2) RU94.38(GND.3) RU94.49(GND.4) RU94.55(S2) U20.3(GND) U22.3(GND) U27.3(GND) U52.AA11(VSSA_USB.2) U52.AB11(VSSA_USB.1) U52.AD10(VSSA_USB3) U52.AD19(VSSA_HDMI.2) U52.AE19(VSSA_HDMI.1) ; also on sheet 3 4 5 7 8 9 10 11 24 25 26 27 28 29 30 31 32 33 34 35 36 37 38 39 40 42 43 46 47 49 50 51 52 53 54 55 56 57 58 60 61 62 63 64 65 66 67 68 69 70 71 72 73 74 75 77 79 80 81 84 85 86 87 88 89
VDDA_1V8_PHY: C486.1 C510.1 C511.1 E9.3 U52.AA13(VDDA_USB1) U52.AB12(VDDA_USB2) U52.W12(VDDA_USB3) ; also on sheet 75 89
VDDA_HDMI: C538.1 C539.1 E9.1 U52.Y17(VDDA_HDMI)
AQSPI1_CS[0]: R747.1 ; also on sheet 4
AQSPI1_D[0]: R741.1 ; also on sheet 4
AQSPI1_D[1]: R743.1 ; also on sheet 4
AQSPI1_D[2]: R739.1 ; also on sheet 4
AQSPI1_D[3]: R737.1 ; also on sheet 4
AQSPI1_RTCLK: R735.1 ; also on sheet 4
AQSPI1_SCLK: R745.1 ; also on sheet 4
B_QSPI1_SCLK: RU32.42(6B2) ; also on sheet 4
C_GPMC_A0: R160.2 RU94.11(5A1)
C_GPMC_A1: R507.2 RU94.13(6A1)
C_GPMC_A2: R504.2 RU94.15(7A1)
C_GPMC_A3: R505.2 RU94.18(8A1)
C_GPMC_A4: R498.2 RU94.21(9A1)
C_GPMC_A5: R503.2 RU94.23(10A1)
C_GPMC_A6: R492.2 RU94.25(11A1)
C_GPMC_A7: R491.2 RU94.27(12A1)
C_GPMC_A8: R501.2 RU33.2(1A1)
C_GPMC_A9: R493.2 RU33.4(2A1)
C_GPMC_A10: R497.2 RU33.6(3A1)
C_GPMC_A11: R502.2 RU33.9(4A1)
C_GPMC_A12: RU33.11(5A1) U52.P4(GPMC_A12)
C_GPMC_A13: R736.1 RU32.2(1A1)
C_GPMC_A14: R738.1 RU32.4(2A1)
C_GPMC_A15: R740.1 RU32.6(3A1)
C_GPMC_A16: R742.1 RU32.9(4A1)
C_GPMC_A17: R744.1 RU32.11(5A1)
C_GPMC_A18: R746.1 RU32.13(6A1)
C_GPMC_A19: RU21.2(1A1) U52.K7(GPMC_A19)
C_GPMC_A20: RU21.4(2A1) U52.M7(GPMC_A20)
C_GPMC_A21: RU21.6(3A1) U52.J5(GPMC_A21)
C_GPMC_A22: RU21.9(4A1) U52.K6(GPMC_A22)
C_GPMC_A23: R495.2 RU21.11(5A1)
C_GPMC_A24: RU21.13(6A1) U52.J4(GPMC_A24)
C_GPMC_A25: RU21.15(7A1) U52.J6(GPMC_A25)
C_GPMC_A26: RU21.18(8A1) U52.H4(GPMC_A26)
C_GPMC_A27: RU21.21(9A1) U52.H5(GPMC_A27)
C_GPMC_D00: R488.1 RU94.9(4A1)
C_GPMC_D01: R165.1 RU94.6(3A1)
C_GPMC_D02: R487.1 RU94.4(2A1)
C_GPMC_D03: R164.1 RU94.2(1A1)
C_GPMC_D04: R496.1 RU88.27(12A1)
C_GPMC_D05: R486.1 RU88.25(11A1)
C_GPMC_D06: R485.1 RU88.23(10A1)
C_GPMC_D07: R167.1 RU88.21(9A1)
C_GPMC_D08: R166.1 RU88.18(8A1)
C_GPMC_D09: R168.1 RU88.15(7A1)
C_GPMC_D10: R169.1 RU88.13(6A1)
C_GPMC_D11: R170.1 RU88.11(5A1)
C_GPMC_D12: R171.1 RU88.9(4A1)
C_GPMC_D13: R484.1 RU88.6(3A1)
C_GPMC_D14: R172.1 RU88.4(2A1)
C_GPMC_D15: R540.1 RU88.2(1A1)
C_GPMC_nCS1: R494.2 RU21.23(10A1)
C_GPMC_nCS2: R748.1 RU32.15(7A1)
C_GPMC_nCS3: R161.2 RU33.27(12A1)
CPU_HDMI_TX0+: U52.AH17(HDMI1_DATA0Y) ; also on sheet 27
CPU_HDMI_TX0-: U52.AG17(HDMI1_DATA0X) ; also on sheet 27
CPU_HDMI_TX1+: U52.AH18(HDMI1_DATA1Y) ; also on sheet 27
CPU_HDMI_TX1-: U52.AG18(HDMI1_DATA1X) ; also on sheet 27
CPU_HDMI_TX2+: U52.AH19(HDMI1_DATA2Y) ; also on sheet 27
CPU_HDMI_TX2-: U52.AG19(HDMI1_DATA2X) ; also on sheet 27
CPU_HDMI_TXC+: U52.AH16(HDMI1_CLOCKY) ; also on sheet 27
CPU_HDMI_TXC-: U52.AG16(HDMI1_CLOCKX) ; also on sheet 27
CPU_VDD_DDR: R812.1 R815.1 ; also on sheet 37 73
DDR1_A0: U52.AD20(DDR1_A0) ; also on sheet 41 42 44
DDR1_A1: U52.AC19(DDR1_A1) ; also on sheet 41 42 44
DDR1_A2: U52.AC20(DDR1_A2) ; also on sheet 41 42 44
DDR1_A3: U52.AB19(DDR1_A3) ; also on sheet 41 42 44
DDR1_A4: U52.AF21(DDR1_A4) ; also on sheet 41 42 44
DDR1_A5: U52.AH22(DDR1_A5) ; also on sheet 41 42 44
DDR1_A6: U52.AG23(DDR1_A6) ; also on sheet 41 42 44
DDR1_A7: U52.AE21(DDR1_A7) ; also on sheet 41 42 44
DDR1_A8: U52.AF22(DDR1_A8) ; also on sheet 41 42 44
DDR1_A9: U52.AE22(DDR1_A9) ; also on sheet 41 42 44
DDR1_A10: U52.AD21(DDR1_A10) ; also on sheet 41 42 44
DDR1_A11: U52.AD22(DDR1_A11) ; also on sheet 41 42 44
DDR1_A12: U52.AC21(DDR1_A12) ; also on sheet 41 42 44
DDR1_A13: U52.AF18(DDR1_A13) ; also on sheet 41 42 44
DDR1_A14: U52.AE17(DDR1_A14) ; also on sheet 41 42 44
DDR1_A15: U52.AD18(DDR1_A15) ; also on sheet 41 42 44
DDR1_BA0: U52.AF17(DDR1_BA0) ; also on sheet 41 42 44
DDR1_BA1: U52.AE18(DDR1_BA1) ; also on sheet 41 42 44
DDR1_BA2: U52.AB18(DDR1_BA2) ; also on sheet 41 42 44
DDR1_CASN: U52.AC18(DDR1_CASN) ; also on sheet 41 42 44
DDR1_CKE: U52.AG22(DDR1_CKE) ; also on sheet 41 42 44
DDR1_CLK0: U52.AG24(DDR1_CK) ; also on sheet 41 42 44
DDR1_CLK0N: U52.AH24(DDR1_NCK) ; also on sheet 41 42 44
DDR1_CSN0: U52.AH23(DDR1_CS0N) ; also on sheet 41 42 44
DDR1_D0: U52.AF25(DDR1_D0) ; also on sheet 42
DDR1_D1: U52.AF26(DDR1_D1) ; also on sheet 42
DDR1_D2: U52.AG26(DDR1_D2) ; also on sheet 42
DDR1_D3: U52.AH26(DDR1_D3) ; also on sheet 42
DDR1_D4: U52.AF24(DDR1_D4) ; also on sheet 42
DDR1_D5: U52.AE24(DDR1_D5) ; also on sheet 42
DDR1_D6: U52.AF23(DDR1_D6) ; also on sheet 42
DDR1_D7: U52.AE23(DDR1_D7) ; also on sheet 42
DDR1_D8: U52.AC23(DDR1_D8) ; also on sheet 42
DDR1_D9: U52.AF27(DDR1_D9) ; also on sheet 42
DDR1_D10: U52.AG27(DDR1_D10) ; also on sheet 42
DDR1_D11: U52.AF28(DDR1_D11) ; also on sheet 42
DDR1_D12: U52.AE26(DDR1_D12) ; also on sheet 42
DDR1_D13: U52.AC25(DDR1_D13) ; also on sheet 42
DDR1_D14: U52.AC24(DDR1_D14) ; also on sheet 42
DDR1_D15: U52.AD25(DDR1_D15) ; also on sheet 42
DDR1_D16: U52.V20(DDR1_D16) ; also on sheet 42
DDR1_D17: U52.W20(DDR1_D17) ; also on sheet 42
DDR1_D18: U52.AB28(DDR1_D18) ; also on sheet 42
DDR1_D19: U52.AC28(DDR1_D19) ; also on sheet 42
DDR1_D20: U52.AC27(DDR1_D20) ; also on sheet 42
DDR1_D21: U52.Y19(DDR1_D21) ; also on sheet 42
DDR1_D22: U52.AB27(DDR1_D22) ; also on sheet 42
DDR1_D23: U52.Y20(DDR1_D23) ; also on sheet 42
DDR1_D24: U52.AA23(DDR1_D24) ; also on sheet 42
DDR1_D25: U52.Y22(DDR1_D25) ; also on sheet 42
DDR1_D26: U52.Y23(DDR1_D26) ; also on sheet 42
DDR1_D27: U52.AA24(DDR1_D27) ; also on sheet 42
DDR1_D28: U52.Y24(DDR1_D28) ; also on sheet 42
DDR1_D29: U52.AA26(DDR1_D29) ; also on sheet 42
DDR1_D30: U52.AA25(DDR1_D30) ; also on sheet 42
DDR1_D31: U52.AA28(DDR1_D31) ; also on sheet 42
DDR1_DQM0: U52.AD23(DDR1_DQM0) ; also on sheet 42
DDR1_DQM1: U52.AB23(DDR1_DQM1) ; also on sheet 42
DDR1_DQM2: U52.AC26(DDR1_DQM2) ; also on sheet 42
DDR1_DQM3: U52.AA27(DDR1_DQM3) ; also on sheet 42
DDR1_DQM_ECC: U52.V26(DDR1_DQM_ECC) ; also on sheet 42
DDR1_DQS0: U52.AH25(DDR1_DQS0) ; also on sheet 42
DDR1_DQS1: U52.AE27(DDR1_DQS1) ; also on sheet 42
DDR1_DQS2: U52.AD27(DDR1_DQS2) ; also on sheet 42
DDR1_DQS3: U52.Y28(DDR1_DQS3) ; also on sheet 42
DDR1_DQS_ECC: U52.V27(DDR1_DQS_ECC) ; also on sheet 42
DDR1_DQSN0: U52.AG25(DDR1_DQSN0) ; also on sheet 42
DDR1_DQSN1: U52.AE28(DDR1_DQSN1) ; also on sheet 42
DDR1_DQSN2: U52.AD28(DDR1_DQSN2) ; also on sheet 42
DDR1_DQSN3: U52.Y27(DDR1_DQSN3) ; also on sheet 42
DDR1_DQSN_ECC: U52.V28(DDR1_DQSN_ECC) ; also on sheet 42
DDR1_ECC_D0: U52.W22(DDR1_ECC_D0) ; also on sheet 42
DDR1_ECC_D1: U52.V23(DDR1_ECC_D1) ; also on sheet 42
DDR1_ECC_D2: U52.W19(DDR1_ECC_D2) ; also on sheet 42
DDR1_ECC_D3: U52.W23(DDR1_ECC_D3) ; also on sheet 42
DDR1_ECC_D4: U52.Y25(DDR1_ECC_D4) ; also on sheet 42
DDR1_ECC_D5: U52.V24(DDR1_ECC_D5) ; also on sheet 42
DDR1_ECC_D6: U52.V25(DDR1_ECC_D6) ; also on sheet 42
DDR1_ECC_D7: U52.Y26(DDR1_ECC_D7) ; also on sheet 42
DDR1_ODT0: U52.AE20(DDR1_ODT0) ; also on sheet 41 42 44
DDR1_RASN: U52.AF20(DDR1_RASN) ; also on sheet 41 42 44
DDR1_RST: R818.1 ; also on sheet 42 71
DDR1_VREF0: C514.1 R811.2 R812.2 R813.2 U52.Y18(DDR1_VREF0)
DDR1_WEN: U52.AH21(DDR1_WEN) ; also on sheet 41 42 44
DDR2_A0: U52.R25(DDR2_A0) ; also on sheet 45 46 48
DDR2_A1: U52.R26(DDR2_A1) ; also on sheet 45 46 48
DDR2_A2: U52.R28(DDR2_A2) ; also on sheet 45 46 48
DDR2_A3: U52.R27(DDR2_A3) ; also on sheet 45 46 48
DDR2_A4: U52.P23(DDR2_A4) ; also on sheet 45 46 48
DDR2_A5: U52.P22(DDR2_A5) ; also on sheet 45 46 48
DDR2_A6: U52.P25(DDR2_A6) ; also on sheet 45 46 48
DDR2_A7: U52.N20(DDR2_A7) ; also on sheet 45 46 48
DDR2_A8: U52.P27(DDR2_A8) ; also on sheet 45 46 48
DDR2_A9: U52.N27(DDR2_A9) ; also on sheet 45 46 48
DDR2_A10: U52.N23(DDR2_A10) ; also on sheet 45 46 48
DDR2_A11: U52.P26(DDR2_A11) ; also on sheet 45 46 48
DDR2_A12: U52.N28(DDR2_A12) ; also on sheet 45 46 48
DDR2_A13: U52.T22(DDR2_A13) ; also on sheet 45 46 48
DDR2_A14: U52.R22(DDR2_A14) ; also on sheet 45 46 48
DDR2_A15: U52.U22(DDR2_A15) ; also on sheet 45 46 48
DDR2_BA0: U52.U23(DDR2_BA0) ; also on sheet 45 46 48
DDR2_BA1: U52.U27(DDR2_BA1) ; also on sheet 45 46 48
DDR2_BA2: U52.U26(DDR2_BA2) ; also on sheet 45 46 48
DDR2_CASN: U52.U28(DDR2_CASN) ; also on sheet 45 46 48
DDR2_CKE: U52.U24(DDR2_CKE) ; also on sheet 45 46 48
DDR2_CLK0: U52.T28(DDR2_CK) ; also on sheet 45 46 48
DDR2_CLK0N: U52.T27(DDR2_NCK) ; also on sheet 45 46 48
DDR2_CSN0: U52.P24(DDR2_CSN0) ; also on sheet 45 46 48
DDR2_D0: U52.E26(DDR2_D0) ; also on sheet 46
DDR2_D1: U52.G25(DDR2_D1) ; also on sheet 46
DDR2_D2: U52.F25(DDR2_D2) ; also on sheet 46
DDR2_D3: U52.F24(DDR2_D3) ; also on sheet 46
DDR2_D4: U52.F26(DDR2_D4) ; also on sheet 46
DDR2_D5: U52.F27(DDR2_D5) ; also on sheet 46
DDR2_D6: U52.E27(DDR2_D6) ; also on sheet 46
DDR2_D7: U52.E28(DDR2_D7) ; also on sheet 46
DDR2_D8: U52.H23(DDR2_D8) ; also on sheet 46
DDR2_D9: U52.H25(DDR2_D9) ; also on sheet 46
DDR2_D10: U52.H24(DDR2_D10) ; also on sheet 46
DDR2_D11: U52.H26(DDR2_D11) ; also on sheet 46
DDR2_D12: U52.G26(DDR2_D12) ; also on sheet 46
DDR2_D13: U52.J25(DDR2_D13) ; also on sheet 46
DDR2_D14: U52.J26(DDR2_D14) ; also on sheet 46
DDR2_D15: U52.J24(DDR2_D15) ; also on sheet 46
DDR2_D16: U52.L22(DDR2_D16) ; also on sheet 46
DDR2_D17: U52.K20(DDR2_D17) ; also on sheet 46
DDR2_D18: U52.K21(DDR2_D18) ; also on sheet 46
DDR2_D19: U52.L23(DDR2_D19) ; also on sheet 46
DDR2_D20: U52.L24(DDR2_D20) ; also on sheet 46
DDR2_D21: U52.J23(DDR2_D21) ; also on sheet 46
DDR2_D22: U52.K22(DDR2_D22) ; also on sheet 46
DDR2_D23: U52.J20(DDR2_D23) ; also on sheet 46
DDR2_D24: U52.L27(DDR2_D24) ; also on sheet 46
DDR2_D25: U52.L26(DDR2_D25) ; also on sheet 46
DDR2_D26: U52.L25(DDR2_D26) ; also on sheet 46
DDR2_D27: U52.L28(DDR2_D27) ; also on sheet 46
DDR2_D28: U52.M23(DDR2_D28) ; also on sheet 46
DDR2_D29: U52.M24(DDR2_D29) ; also on sheet 46
DDR2_D30: U52.M25(DDR2_D30) ; also on sheet 46
DDR2_D31: U52.M26(DDR2_D31) ; also on sheet 46
DDR2_DQM0: U52.F28(DDR2_DQM0) ; also on sheet 46
DDR2_DQM1: U52.G24(DDR2_DQM1) ; also on sheet 46
DDR2_DQM2: U52.K23(DDR2_DQM2) ; also on sheet 46
DDR2_DQM3: U52.M22(DDR2_DQM3) ; also on sheet 46
DDR2_DQS0: U52.G28(DDR2_DQS0) ; also on sheet 46
DDR2_DQS1: U52.H27(DDR2_DQS1) ; also on sheet 46
DDR2_DQS2: U52.K27(DDR2_DQS2) ; also on sheet 46
DDR2_DQS3: U52.M28(DDR2_DQS3) ; also on sheet 46
DDR2_DQSN0: U52.G27(DDR2_DQSn0) ; also on sheet 46
DDR2_DQSN1: U52.H28(DDR2_DQSN1) ; also on sheet 46
DDR2_DQSN2: U52.K28(DDR2_DQSN2) ; also on sheet 46
DDR2_DQSN3: U52.M27(DDR2_DQSN3) ; also on sheet 46
DDR2_ODT0: U52.R23(DDR2_ODT0) ; also on sheet 45 46 48
DDR2_RASN: U52.T23(DDR2_RASN) ; also on sheet 45 46 48
DDR2_RST: R817.1 ; also on sheet 46 71
DDR2_VREF0: C147.1 R814.2 R815.2 R816.2 U52.N22(DDR2_VREF0)
DDR2_WEN: U52.U25(DDR2_WEN) ; also on sheet 45 46 48
DDR_VREFSTL1: R811.1 ; also on sheet 42 70
DDR_VREFSTL2: R814.1 ; also on sheet 46 70
EVM_3V3: C69.1 C84.1 C85.1 C297.1 C298.1 C308.1 C312.1 C322.1 R80.1 R81.1 R82.1 R83.1 R84.1 R85.1 R86.1 R87.1 R88.1 R89.1 R90.1 R91.1 R92.1 R93.1 R94.1 R95.1 R163.1 R201.1 R215.1 R234.1 R239.1 R383.1 R458.1 R459.1 R470.1 R756.1 R757.1 R766.1 RU21.17(VCC.1) RU32.17(VCC.1) RU33.17(VCC.1) RU88.17(VCC.1) RU94.17(VCC.1) U20.5(VCC) U22.5(VCC) U27.5(VCC) ; also on sheet 3 4 5 7 8 9 10 11 24 25 26 27 28 29 30 31 32 33 49 50 51 52 53 56 57 58 60 61 69 70 78 84 85 86 87 88
FORCE_EMU: R215.2 SW5.14 ; also on sheet 9
GP2[27]: U52.M4(GPMC_BEN1) ; also on sheet 61
GPMC_A1: RU94.43(6B1) ; also on sheet 7
GPMC_A2: RU94.41(7B1) ; also on sheet 7
GPMC_A3: RU94.39(8B1) ; also on sheet 7
GPMC_A4: RU94.36(9B1) ; also on sheet 7
GPMC_A5: RU94.34(10B1) ; also on sheet 7
GPMC_A6: RU94.32(11B1) ; also on sheet 7
GPMC_A7: RU94.30(12B1) ; also on sheet 7
GPMC_A8: RU33.54(1B1) ; also on sheet 7
GPMC_A9: RU33.52(2B1) ; also on sheet 7
GPMC_A10: RU33.50(3B1) ; also on sheet 7
GPMC_A11: RU33.47(4B1) ; also on sheet 7
GPMC_A12: RU33.45(5B1) ; also on sheet 7
GPMC_A13: RU32.54(1B1) ; also on sheet 7
GPMC_A14: RU32.52(2B1) ; also on sheet 7
GPMC_A15: RU32.50(3B1) ; also on sheet 7
GPMC_A16: RU32.47(4B1) ; also on sheet 7
GPMC_A17: RU32.45(5B1) ; also on sheet 7
GPMC_A18: RU32.43(6B1) ; also on sheet 7
GPMC_A19: RU21.54(1B1) ; also on sheet 7
GPMC_A20: RU21.52(2B1) ; also on sheet 7
GPMC_A21: RU21.50(3B1) ; also on sheet 7
GPMC_A22: RU21.47(4B1) ; also on sheet 7
GPMC_A23: RU21.45(5B1) ; also on sheet 7
GPMC_A24: RU21.43(6B1) ; also on sheet 7
GPMC_A25: RU21.41(7B1) ; also on sheet 7
GPMC_A26: RU21.39(8B1) ; also on sheet 7
GPMC_ADVn_ALE: U52.N1(GPMC_ADVN_ALE) ; also on sheet 5
GPMC_BE0n_CLE: U52.N6(GPMC_BEN0) ; also on sheet 5
GPMC_D00: R110.1 RU94.47(4B1) SW2.1(A1) ; also on sheet 5 7
GPMC_D01: R111.1 RU94.50(3B1) SW2.2(A2) ; also on sheet 5 7
GPMC_D02: R112.1 RU94.52(2B1) SW2.3(A3) ; also on sheet 5 7
GPMC_D03: R113.1 RU94.54(1B1) SW2.4(A4) ; also on sheet 5 7
GPMC_D04: R114.1 RU88.30(12B1) SW2.5(A5) ; also on sheet 5 7
GPMC_D05: R115.1 RU88.32(11B1) SW2.6(A6) ; also on sheet 5 7
GPMC_D06: R116.1 RU88.34(10B1) SW2.7(A7) ; also on sheet 5 7
GPMC_D07: R117.1 RU88.36(9B1) SW2.8(A8) ; also on sheet 5 7
GPMC_D08: R118.1 RU88.39(8B1) SW3.1(A1) ; also on sheet 5 7
GPMC_D09: R119.1 RU88.41(7B1) SW3.2(A2) ; also on sheet 5 7
GPMC_D10: R120.1 RU88.43(6B1) SW3.3(A3) ; also on sheet 5 7
GPMC_D11: R121.1 RU88.45(5B1) SW3.4(A4) ; also on sheet 5 7
GPMC_D12: R122.1 RU88.47(4B1) SW3.5(A5) ; also on sheet 5 7
GPMC_D13: R123.1 RU88.50(3B1) SW3.6(A6) ; also on sheet 5 7
GPMC_D14: R124.1 RU88.52(2B1) SW3.7(A7) ; also on sheet 5 7
GPMC_D15: R125.1 RU88.54(1B1) SW3.8(A8) ; also on sheet 5 7
GPMC_nCS0: R158.2 ; also on sheet 5 7
GPMC_OEN_REN: R489.2 ; also on sheet 5 7
GPMC_WAIT: R163.2 U52.N2(GPMC_WAIT0) ; also on sheet 5
GPMC_WEn: R490.2 ; also on sheet 5 7
GPMC_WPN: R756.2 SW5.12 ; also on sheet 5
I2C_EEPROM_WP: R757.2 SW5.11 ; also on sheet 88
LCD_B0: R598.1 ; also on sheet 26
LCD_B1: R213.1 ; also on sheet 26
LCD_B2: R217.1 ; also on sheet 26 32
LCD_B3: R218.1 ; also on sheet 26 32
LCD_B4: R572.1 ; also on sheet 26 32
LCD_B5: R556.1 ; also on sheet 26 32
LCD_B6: R564.1 ; also on sheet 26 32
LCD_B7: R542.1 ; also on sheet 26 32
LCD_DE: R212.1 ; also on sheet 26
LCD_G0: R544.1 ; also on sheet 26
LCD_G1: R563.1 ; also on sheet 26
LCD_G2: R551.1 ; also on sheet 26 32
LCD_G3: R545.1 ; also on sheet 26 32
LCD_G4: R188.1 ; also on sheet 26 32
LCD_G5: R552.1 ; also on sheet 26 32
LCD_G6: R550.1 ; also on sheet 26 32
LCD_G7: R557.1 ; also on sheet 26 32
LCD_HS: R582.1 ; also on sheet 26
LCD_PCLK: R586.1 ; also on sheet 26
LCD_R0: R189.1 ; also on sheet 26
LCD_R1: R199.1 ; also on sheet 26
LCD_R2: R197.1 ; also on sheet 26 32
LCD_R3: R198.1 ; also on sheet 26 32
LCD_R4: R571.1 ; also on sheet 26 32
LCD_R5: R203.1 ; also on sheet 26 32
LCD_R6: R202.1 ; also on sheet 26 32
LCD_R7: R220.1 ; also on sheet 26 32
LCD_VS: R595.1 ; also on sheet 26
MCASP1_ENn: R766.2 SW5.15 ; also on sheet 9 52
MMC2_BOOTn: R459.2 RU21.1(S0) SW5.18 U20.2(I) ; also on sheet 9 35
MMC2_CLK: RU21.44(5B2) ; also on sheet 8
MMC2_CMD: RU21.33(10B2) ; also on sheet 8
MMC2_DAT0: RU21.42(6B2) ; also on sheet 8
MMC2_DAT1: RU21.40(7B2) ; also on sheet 8
MMC2_DAT2: RU21.37(8B2) ; also on sheet 8
MMC2_DAT3: RU21.35(9B2) ; also on sheet 8
MMC2_DAT4: RU21.53(1B2) ; also on sheet 8
MMC2_DAT5: RU21.51(2B2) ; also on sheet 8
MMC2_DAT6: RU21.48(3B2) ; also on sheet 8
MMC2_DAT7: RU21.46(4B2) ; also on sheet 8
NAND_BOOTn: R239.2 SW5.20 ; also on sheet 5 9
NOR_BOOTn: R234.2 SW5.19 ; also on sheet 7 9
PCI_RESET_SEL: R201.2 SW5.13 ; also on sheet 31
QSPI1_CS[0]: RU32.40(7B2) ; also on sheet 4
QSPI1_D[0]: RU32.46(4B2) ; also on sheet 4
QSPI1_D[1]: RU32.44(5B2) ; also on sheet 4
QSPI1_D[2]: RU32.48(3B2) ; also on sheet 4
QSPI1_D[3]: RU32.51(2B2) ; also on sheet 4
QSPI1_RTCLK: RU32.53(1B2) ; also on sheet 4
QSPI_BOOT: R470.2 RU32.1(S0) SW5.17 U27.2(I) ; also on sheet 9
RC_C_GPMC_nCS1: R494.1 U52.H6(GPMC_CS1)
RC_GPMC_A0: R160.1 U52.R6(GPMC_A0)
RC_GPMC_A1: R507.1 U52.T9(GPMC_A1)
RC_GPMC_A2: R504.1 U52.T6(GPMC_A2)
RC_GPMC_A3: R505.1 U52.T7(GPMC_A3)
RC_GPMC_A4: R498.1 U52.P6(GPMC_A4)
RC_GPMC_A5: R503.1 U52.R9(GPMC_A5)
RC_GPMC_A6: R492.1 U52.R5(GPMC_A6)
RC_GPMC_A7: R491.1 U52.P5(GPMC_A7)
RC_GPMC_A8: R501.1 U52.N7(GPMC_A8)
RC_GPMC_A9: R493.1 U52.R4(GPMC_A9)
RC_GPMC_A10: R497.1 U52.N9(GPMC_A10)
RC_GPMC_A11: R502.1 U52.P9(GPMC_A11)
RC_GPMC_A13: R735.2 R736.2 U52.R3(GPMC_A13)
RC_GPMC_A14: R737.2 R738.2 U52.T2(GPMC_A14)
RC_GPMC_A15: R739.2 R740.2 U52.U2(GPMC_A15)
RC_GPMC_A16: R741.2 R742.2 U52.U1(GPMC_A16)
RC_GPMC_A17: R743.2 R744.2 U52.P3(GPMC_A17)
RC_GPMC_A18: R745.2 R746.2 U52.R2(GPMC_A18)
RC_GPMC_A23: R495.1 U52.J7(GPMC_A23)
RC_GPMC_D00: R488.2 U52.M6(GPMC_AD0)
RC_GPMC_D01: R165.2 U52.M2(GPMC_AD1)
RC_GPMC_D02: R487.2 U52.L5(GPMC_AD2)
RC_GPMC_D03: R164.2 U52.M1(GPMC_AD3)
RC_GPMC_D04: R496.2 U52.L6(GPMC_AD4)
RC_GPMC_D05: R486.2 U52.L4(GPMC_AD5)
RC_GPMC_D06: R485.2 U52.L3(GPMC_AD6)
RC_GPMC_D07: R167.2 U52.L2(GPMC_AD7)
RC_GPMC_D08: R166.2 U52.L1(GPMC_AD8)
RC_GPMC_D09: R168.2 U52.K2(GPMC_AD9)
RC_GPMC_D10: R169.2 U52.J1(GPMC_AD10)
RC_GPMC_D11: R170.2 U52.J2(GPMC_AD11)
RC_GPMC_D12: R171.2 U52.H1(GPMC_AD12)
RC_GPMC_D13: R484.2 U52.J3(GPMC_AD13)
RC_GPMC_D14: R172.2 U52.H2(GPMC_AD14)
RC_GPMC_D15: R540.2 U52.H3(GPMC_AD15)
RC_GPMC_nCS0: R158.1 U52.T1(GPMC_CS0)
RC_GPMC_nCS2: R747.2 R748.2 U52.P2(GPMC_CS2)
RC_GPMC_nCS3: R161.1 U52.P1(GPMC_CS3)
RC_GPMC_OEN_REn: R489.1 U52.M5(GPMC_OEN_REN)
RC_GPMC_WEn: R490.1 U52.M3(GPMC_WEN)
SEL_GPMC_AD_VID_S0: R458.2 RU33.1(S0) RU88.1(S0) RU94.1(S0) U22.2(I) ; also on sheet 9
SEL_GPMC_AD_VID_S1: RU33.56(S1) RU88.56(S1) RU94.56(S1) U22.4(O)
UART_SEL1_3: R383.2 SW5.16 ; also on sheet 9 51
USB1_DM: U52.AC12(USB1_DM) ; also on sheet 50
USB1_DP: U52.AD12(USB1_DP) ; also on sheet 50
USB1_DRV_VBUS: U52.AB10(USB1_DRVVBUS) ; also on sheet 49
USB2_DM: U52.AF11(USB2_DM) ; also on sheet 50
USB2_DP: U52.AE11(USB2_DP) ; also on sheet 50
USB2_DRV_VBUS: U52.AC10(USB2_DRVVBUS) ; also on sheet 49
USB_RXN0: U52.AF12(USB_RXN0) ; also on sheet 50
USB_RXP0: U52.AE12(USB_RXP0) ; also on sheet 50
USB_TXN0: U52.AC11(USB_TXN0) ; also on sheet 50
USB_TXP0: U52.AD11(USB_TXP0) ; also on sheet 50
VOUT3B_CLK: RU33.29(12B2) ; also on sheet 28
VOUT3B_D0: RU94.46(4B2) ; also on sheet 28
VOUT3B_D1: RU94.48(3B2) ; also on sheet 28
VOUT3B_D2: RU94.51(2B2) ; also on sheet 28
VOUT3B_D3: RU94.53(1B2) ; also on sheet 28
VOUT3B_D4: RU88.29(12B2) ; also on sheet 28
VOUT3B_D5: RU88.31(11B2) ; also on sheet 28
VOUT3B_D6: RU88.33(10B2) ; also on sheet 28
VOUT3B_D7: RU88.35(9B2) ; also on sheet 28
VOUT3B_D8: RU88.37(8B2) ; also on sheet 28
VOUT3B_D9: RU88.40(7B2) ; also on sheet 28
VOUT3B_D10: RU88.42(6B2) ; also on sheet 28
VOUT3B_D11: RU88.44(5B2) ; also on sheet 28
VOUT3B_D12: RU88.46(4B2) ; also on sheet 28
VOUT3B_D13: RU88.48(3B2) ; also on sheet 28
VOUT3B_D14: RU88.51(2B2) ; also on sheet 28
VOUT3B_D15: RU88.53(1B2) ; also on sheet 28
VOUT3B_D16: RU94.44(5B2) ; also on sheet 28
VOUT3B_D17: RU94.42(6B2) ; also on sheet 28
VOUT3B_D18: RU94.40(7B2) ; also on sheet 28
VOUT3B_D19: RU94.37(8B2) ; also on sheet 28
VOUT3B_D20: RU94.35(9B2) ; also on sheet 28
VOUT3B_D21: RU94.33(10B2) ; also on sheet 28
VOUT3B_D22: RU94.31(11B2) ; also on sheet 28
VOUT3B_D23: RU94.29(12B2) ; also on sheet 28
VOUT3B_DE: RU33.48(3B2) ; also on sheet 28
VOUT3B_HSYNC: RU33.53(1B2) ; also on sheet 28
VOUT3B_INTB: RU33.46(4B2) ; also on sheet 28
VOUT3B_VSYNC: RU33.51(2B2) ; also on sheet 28
VUSB_3V3: C439.1 C440.1 C451.1 C489.1 U52.AA12(VDDA33V_USB1) U52.Y12(VDDA33V_USB2) ; also on sheet 77
N18148112: R717.2 RU21.3(1A2) RU21.5(2A2) RU21.7(3A2) RU21.10(4A2) RU21.12(5A2) RU21.14(6A2) RU21.16(7A2) RU21.20(8A2) RU21.22(9A2) RU21.24(10A2) RU21.25(11A1) RU21.26(11A2) RU21.27(12A1) RU21.28(12A2)
N18148316: R718.2 RU33.3(1A2) RU33.5(2A2) RU33.7(3A2) RU33.10(4A2) RU33.12(5A2) RU33.13(6A1) RU33.14(6A2) RU33.15(7A1) RU33.16(7A2) RU33.18(8A1) RU33.20(8A2) RU33.21(9A1) RU33.22(9A2) RU33.23(10A1) RU33.24(10A2) RU33.25(11A1) RU33.26(11A2) RU33.28(12A2)
N18149020: R720.2 RU94.3(1A2) RU94.5(2A2) RU94.7(3A2) RU94.10(4A2) RU94.12(5A2) RU94.14(6A2) RU94.16(7A2) RU94.20(8A2) RU94.22(9A2) RU94.24(10A2) RU94.26(11A2) RU94.28(12A2)
N18149133: R719.2 RU88.3(1A2) RU88.5(2A2) RU88.7(3A2) RU88.10(4A2) RU88.12(5A2) RU88.14(6A2) RU88.16(7A2) RU88.20(8A2) RU88.22(9A2) RU88.24(10A2) RU88.26(11A2) RU88.28(12A2)
N18150924: R725.2 RU32.3(1A2) RU32.5(2A2) RU32.7(3A2) RU32.10(4A2) RU32.12(5A2) RU32.14(6A2) RU32.16(7A2) RU32.18(8A1) RU32.20(8A2) RU32.21(9A1) RU32.22(9A2) RU32.23(10A1) RU32.24(10A2) RU32.25(11A1) RU32.26(11A2) RU32.27(12A1) RU32.28(12A2)
N19240062: R85.2 SW2.11(B6)
N19240090: R86.2 SW2.10(B7)
N19240118: R87.2 SW2.9(B8)
N19692324: R80.2 SW2.16(B1)
N19692326: R81.2 SW2.15(B2)
N19692328: R82.2 SW2.14(B3)
N19692409: R83.2 SW2.13(B4)
N19692411: R84.2 SW2.12(B5)
N23038409: R598.2 U52.F11(VOUT1_D0)
N23038410: R213.2 U52.G10(VOUT1_D1)
N23038411: R217.2 U52.F10(VOUT1_D2)
N23038412: R218.2 U52.G11(VOUT1_D3)
N23038413: R572.2 U52.E9(VOUT1_D4)
N23038414: R556.2 U52.F9(VOUT1_D5)
N23038415: R564.2 U52.F8(VOUT1_D6)
N23038416: R542.2 U52.E7(VOUT1_D7)
N23038769: R544.2 U52.E8(VOUT1_D8)
N23038770: R563.2 U52.D9(VOUT1)
N23038771: R551.2 U52.D7(VOUT1_D10)
N23038772: R545.2 U52.D8(VOUT1_D11)
N23038773: R188.2 U52.A5(VOUT1_D12)
N23038774: R552.2 U52.C6(VOUT1_D13)
N23038775: R550.2 U52.C8(VOUT1_D14)
N23038776: R557.2 U52.C7(VOUT1_D15)
N23039129: R189.2 U52.B7(VOUT1_D16)
N23039130: R199.2 U52.B8(VOUT1_D17)
N23039131: R197.2 U52.A7(VOUT1_D18)
N23039132: R198.2 U52.A8(VOUT1_D19)
N23039133: R571.2 U52.C9(VOUT1_D20)
N23039134: R203.2 U52.A9(VOUT1_D21)
N23039135: R202.2 U52.B9(VOUT1_D22)
N23039136: R220.2 U52.A10(VOUT1_D23)
N23042575: R586.2 U52.D11(VOUT1_CLK)
N23042576: R582.2 U52.C11(VOUT1_HSYNC)
N23042577: R595.2 U52.E11(VOUT1_VSYNC)
N23042578: R212.2 U52.B10(VOUT1_DE)
N23128401: R817.2 U52.R24(DDR2_RST)
N23128428: R818.2 U52.AG21(DDR1_RST)
N28760816: RU21.56(S1) U20.4(O)
N29190185: RU32.56(S1) U27.4(O)
N30079472: R88.2 SW3.16(B1)
N30079474: R89.2 SW3.15(B2)
N30136123: R90.2 SW3.14(B3)
N30136125: R91.2 SW3.13(B4)
N30139026: R92.2 SW3.12(B5)
N30139028: R93.2 SW3.11(B6)
N30141933: R94.2 SW3.10(B7)
N30141935: R95.2 SW3.9(B8)
N32448034: R585.2 SW5.8
N32450953: R594.2 SW5.7
N32453874: R599.2 SW5.6
N32462658: R612.2 SW5.2
N32462660: R619.2 SW5.1
N32462662: R610.2 SW5.3
N32468327: R604.2 SW5.4
N32471262: R601.2 SW5.5
N43244613: R579.2 SW5.9
N43259312: R569.2 SW5.10
N45290070: TP38.1 U52.P7(GPMC_CLK)
N45378434: TP50.1 U52.B11(VOUT1_FLD)

Not connected (* = marked no-connect by the designer): RU21 29(12B2) 30(12B1) 31(11B2) 32(11B1) 34(10B1) 36(9B1); RU32 29(12B2) 30(12B1) 31(11B2) 32(11B1) 33(10B2) 34(10B1) 35(9B2) 36(9B1) 37(8B2) 39(8B1) 41(7B1); RU33 30(12B1) 31(11B2) 32(11B1) 33(10B2) 34(10B1) 35(9B2) 36(9B1) 37(8B2) 39(8B1) 40(7B2) 41(7B1) 42(6B2) 43(6B1) 44(5B2); RU94 45(5B1); U20 1(NC1); U22 1(NC1); U27 1(NC1)

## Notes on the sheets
sheet 13
- DIFFERENTIAL PAIR
  90 OHM DIFFERENTIAL
  IMPEDANCE
  SHORT AND STRAIGHT AS
  POSSIBLE,
  MINIMUM NUMBER OF VIAS
- 3.3 VOLT
- 1.8 VOLT
sheet 14
- gpmc_ad[0]
  gpmc_ad[1]
  gpmc_ad[2]
  gpmc_ad[3]
  gpmc_ad[4]
  gpmc_ad[5]
  gpmc_ad[6]
  gpmc_ad[7]
  gpmc_ad[8]
  gpmc_ad[9]
  gpmc_ad[10]
  gpmc_ad[11]
  gpmc_ad[12]
  gpmc_ad[13]
  gpmc_ad[14]
  gpmc_ad[15]
  gpmc_a[0]
  gpmc_a[1]
  gpmc_a[2]
  gpmc_a[3]
  gpmc_a[4]
  gpmc_a[5]
  gpmc_a[6]
  gpmc_a[7]
  gpmc_a[8]
  gpmc_a[9]
  gpmc_a[10]
  gpmc_a[11]
- vout3_d[0]
  vout3_d[1]
  vout3_d[2]
  vout3_d[3]
  vout3_d[4]
  vout3_d[5]
  vout3_d[6]
  vout3_d[7]
  vout3_d[8]
  vout3_d[9]
  vout3_d[10]
  vout3_d[11]
  vout3_d[12]
  vout3_d[13]
  vout3_d[14]
  vout3_d[15]
  vout3_d[16]
  vout3_d[17]
  vout3_d[18]
  vout3_d[19]
  vout3_d[20]
  vout3_d[21]
  vout3_d[22]
  vout3_d[23]
  vout3_hsync
  vout3_vsync
  vout3_de
  vout3_fld
- gpmc_a[19]
  gpmc_a[20]
  gpmc_a[21]
  gpmc_a[22]
  gpmc_a[23]
  gpmc_a[24]
  gpmc_a[25]
  gpmc_a[26]
  gpmc_a[27]
  gpmc_cs[1]
- mmc2_dat[4]
  mmc2_dat[5]
  mmc2_dat[6]
  mmc2_dat[7]
  mmc2_clk
  mmc2_dat[0]
  mmc2_dat[1]
  mmc2_dat[2]
  mmc2_dat[3]
  mmc2_cmd
- gpmc_a[13]
  gpmc_a[14]
  gpmc_a[15]
  gpmc_a[16]
  gpmc_a[17]
  gpmc_a[18]
- QSPI1	qspi1_rtclk
  QSPI1	qspi1_d[3]
  QSPI1	qspi1_d[2]
  QSPI1	qspi1_d[0]
  QSPI1	qspi1_d[1]
  QSPI1	qspi1_sclk
- AQSPI PATH IS THE FAST PATH WITH MAX TRACE LENGTH OF
  2.75 INCHES.  THIS RESISTOR POPULATIONS IS ON BOTH
  ENDS OF THE NET.  THE OTHER END IS THE SPI FLASH U18.
- gpmc_cs[3]
- vout3_clk
sheet 15
- FUNCTION TABLE
  INPUTS      INPUTS/OUTPUTS        FUNCTION
  S2 S1 S0          A1 A2
  L L L             Z Z               Disconnect
  L L H             B1 Z          A1 port = B1 port
  L H L             B2 Z          A1 port = B2 port
  L H H             Z B1          A2 port = B1 port
  H L L             Z B2          A2 port = B2 port
  H L H             Z Z           Disconnect
  H H L             B1 B2         A1 port = B1 port
                                  A2 port = B2 port
  H H H             B2 B1         A1 port = B2 port
                                  A2 port = B1 port
- DEFAULTS TO GPMC FOR BOOTING
- gpmc_ad[0]
  gpmc_ad[1]
  gpmc_ad[2]
  gpmc_ad[3]
  gpmc_ad[4]
  gpmc_ad[5]
  gpmc_ad[6]
  gpmc_ad[7]
  gpmc_ad[8]
  gpmc_ad[9]
  gpmc_ad[10]
  gpmc_ad[11]
  gpmc_ad[12]
  gpmc_ad[13]
  gpmc_ad[14]
  gpmc_ad[15]
  gpmc_a[0]
  gpmc_a[1]
  gpmc_a[2]
  gpmc_a[3]
  gpmc_a[4]
  gpmc_a[5]
  gpmc_a[6]
  gpmc_a[7]
  gpmc_a[8]
  gpmc_a[9]
  gpmc_a[10]
  gpmc_a[11]
- vout3_d[0]
  vout3_d[1]
  vout3_d[2]
  vout3_d[3]
  vout3_d[4]
  vout3_d[5]
  vout3_d[6]
  vout3_d[7]
  vout3_d[8]
  vout3_d[9]
  vout3_d[10]
  vout3_d[11]
  vout3_d[12]
  vout3_d[13]
  vout3_d[14]
  vout3_d[15]
  vout3_d[16]
  vout3_d[17]
  vout3_d[18]
  vout3_d[19]
  vout3_d[20]
  vout3_d[21]
  vout3_d[22]
  vout3_d[23]
  vout3_hsync
  vout3_vsync
  vout3_de
  vout3_fld
- gpmc_cs[3]
- vout3_clk
sheet 16
- DEFAULTS TO GPMC FOR BOOTING
- REV E
- gpmc_ad[0]
  gpmc_ad[1]
  gpmc_ad[2]
  gpmc_ad[3]
  gpmc_ad[4]
  gpmc_ad[5]
  gpmc_ad[6]
  gpmc_ad[7]
  gpmc_ad[8]
  gpmc_ad[9]
  gpmc_ad[10]
  gpmc_ad[11]
  gpmc_ad[12]
  gpmc_ad[13]
  gpmc_ad[14]
  gpmc_ad[15]
  gpmc_a[0]
  gpmc_a[1]
  gpmc_a[2]
  gpmc_a[3]
  gpmc_a[4]
  gpmc_a[5]
  gpmc_a[6]
  gpmc_a[7]
  gpmc_a[8]
  gpmc_a[9]
  gpmc_a[10]
  gpmc_a[11]
- vout3_d[0]
  vout3_d[1]
  vout3_d[2]
  vout3_d[3]
  vout3_d[4]
  vout3_d[5]
  vout3_d[6]
  vout3_d[7]
  vout3_d[8]
  vout3_d[9]
  vout3_d[10]
  vout3_d[11]
  vout3_d[12]
  vout3_d[13]
  vout3_d[14]
  vout3_d[15]
  vout3_d[16]
  vout3_d[17]
  vout3_d[18]
  vout3_d[19]
  vout3_d[20]
  vout3_d[21]
  vout3_d[22]
  vout3_d[23]
  vout3_hsync
  vout3_vsync
  vout3_de
  vout3_fld
- gpmc_cs[3]
- vout3_clk
sheet 17
- gpmc_a[19]
  gpmc_a[20]
  gpmc_a[21]
  gpmc_a[22]
  gpmc_a[23]
  gpmc_a[24]
  gpmc_a[25]
  gpmc_a[26]
  gpmc_a[27]
  gpmc_cs[1]
- mmc2_dat[4]
  mmc2_dat[5]
  mmc2_dat[6]
  mmc2_dat[7]
  mmc2_clk
  mmc2_dat[0]
  mmc2_dat[1]
  mmc2_dat[2]
  mmc2_dat[3]
  mmc2_cmd
- DEFAULTS TO GPMC FOR BOOTING
- USE MMC2 BOOT SWITCH TO OVER RIDE
- DEFAULTS TO GPMC FOR BOOTING
- USE QSPI BOOT SWITCH TO OVER RIDE
- gpmc_a[13]
  gpmc_a[14]
  gpmc_a[15]
  gpmc_a[16]
  gpmc_a[17]
  gpmc_a[18]
- QSPI1	qspi1_rtclk
  QSPI1	qspi1_d[3]
  QSPI1	qspi1_d[2]
  QSPI1	qspi1_d[0]
  QSPI1	qspi1_d[1]
  QSPI1	qspi1_sclk
- gpmc_cs[2]
- qspi1_cs[0]
sheet 18
- MMC2 BOOT PULL UP ON PAGE 23 SET TO LOGIC 0 TO
   ENABLE MMC2 MUX FOR BOOTING SET TO 1 FOR GPMC
  BOOTING
- QSPI BOOT PULL UP ON PAGE 23 SET TO LOGIC 0 TO
   ENABLE QSPI MUX FOR BOOTING SET TO 1 FOR GPMC
  BOOTING
- UART SEL1_3 PULL UP ON PAGE 58 SELECTS UART3
  MUX INPUT TO BE USART PORT AT MINI_USB A(J1)
  DURING BOOTING.
  MCASP1_ENn MUST BE SET TO LOGIC 1 TO DISABLE
  COM8. ALSO OTHER MUX NEEDS TO BE IN DEFAULT
  CONFIGURATION
sheet 19
- EACH DATA GROUP IS MATCHED WITHIN THE GROUP
- differential pairs 100 ohm
- 6 places
- Data Group 0-0
- USE 4X SPACING TRACE
  TO TRACE EQUAL LENGTH
  +/-5 MIL
- Data Group 0-1
- USE 4X SPACING TRACE
  TO TRACE EQUAL LENGTH
  +/-5 MIL
- Data Group 0-2
- USE 4X SPACING TRACE
  TO TRACE EQUAL LENGTH
  +/-5 MIL
- Data Group 0-3
- USE 4X SPACING TRACE
  TO TRACE EQUAL LENGTH
  +/-5 MIL
- ER18
sheet 20
- EACH DATA GROUP IS MATCHED WITHIN THE GROUP
- differential pairs 100 ohm
- 5 places
- Data Group 2-0
- USE 4X SPACING TRACE
  TO TRACE EQUAL LENGTH
  +/-5 MIL
- CONTROL GROUP 2
- Data Group 2-1
- USE 4X SPACING TRACE
  TO TRACE EQUAL LENGTH
  +/-5 MIL
- USE 4X SPACING TRACE
  TO TRACE EQUAL LENGTH
  +/-5 MIL
- Data Group 2-2
- USE 4X SPACING TRACE
  TO TRACE EQUAL LENGTH
  +/-5 MIL
- Data Group 2-3
- CLOCK GROUP 2
- USE 4X SPACING TRACE
  TO TRACE EQUAL LENGTH
  +/-5 MIL
- ER18
- WARNING [DRC0006]   Net has fewer than two connections N23667068:  VAYU_EVM, SH26 - VAYU DDR EMIF2 INTERFACE  (3.20, 4.00)
  WARNING [DRC0006]   Net has fewer than two connections N23667055:  VAYU_EVM, SH26 - VAYU DDR EMIF2 INTERFACE  (3.20, 2.40)
  WARNING [DRC0006]   Net has fewer than two connections N25725225:  VAYU_EVM, SH25 - VAYU DDR EMIF1 INTERFACE  (3.10, 3.50)
  WARNING [DRC0006]   Net has fewer than two connections N25725223:  VAYU_EVM, SH25 - VAYU DDR EMIF1 INTERFACE  (3.10, 2.20)
- DDR2_RST is not part of group
- DDR_VREFSSTL is not part of group
sheet 21
- 1.8 VOLT
sheet 22
- 22 OHM OK FOR LCD AS IT IS NOT GOING THROUGH MUXES.
- LCD_B2 = EMU2 TRACE CLOCK
